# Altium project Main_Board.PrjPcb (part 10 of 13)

## Sheet RJ45.SchDoc: Ethernet
size A3; Organization: Altium Limited; Address1: L3, 12a Rodborough Rd; Address2: Frenchs Forest; Address3: NSW; Address4: Australia 2086
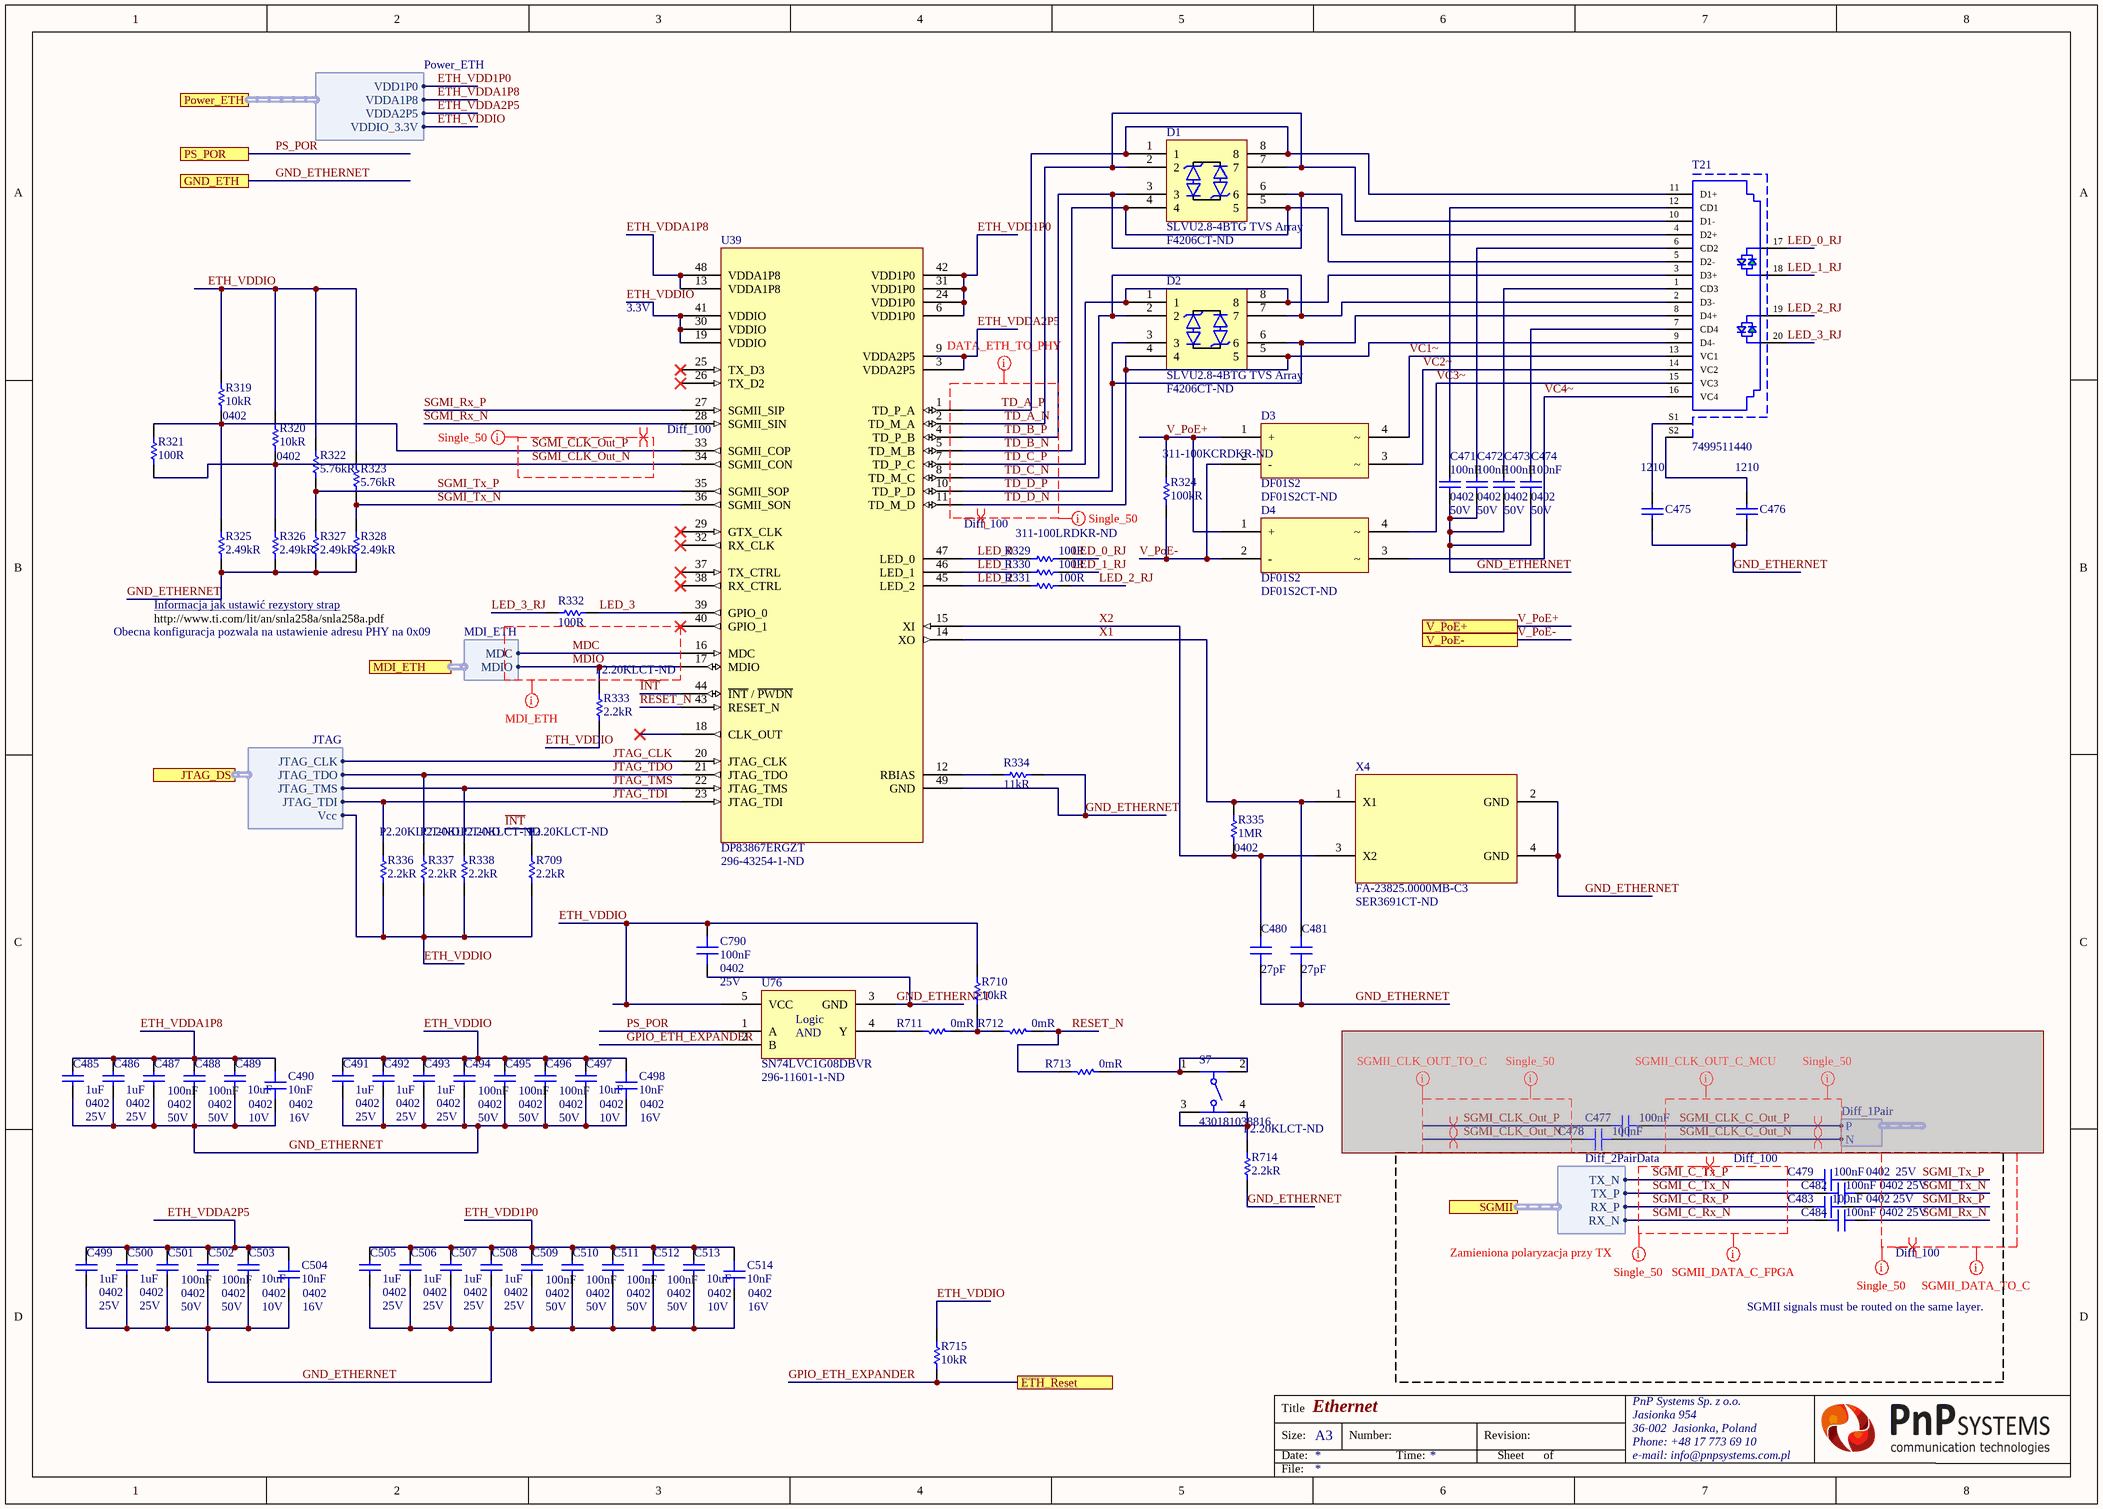
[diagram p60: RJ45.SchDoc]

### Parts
(Parts that share a designator on the sheet are numbered #1, #2 ... from top to bottom, then left to right.)
C471  100nF  Case Code (Imperial): 0402  Voltage: 50V  [CAP 0402/1005 KK]
C472  100nF  Case Code (Imperial): 0402  Voltage: 50V  [CAP 0402/1005 KK]
C473  100nF  Case Code (Imperial): 0402  Voltage: 50V  [CAP 0402/1005 KK]
C474  100nF  Case Code (Imperial): 0402  Voltage: 50V  [CAP 0402/1005 KK]
C475  Case/Package: 1210  [CAPC3326X17L]  (hidden comment: Capacitor_1210)
C476  Case/Package: 1210  [CAPC3326X17L]  (hidden comment: Capacitor_1210)
C477#2  100nF  [CAP 0402/1005 KK]  (masked out: inside a compile mask, not in the netlist)
C478#2  100nF  [CAP 0402/1005 KK]  (masked out: inside a compile mask, not in the netlist)
C479  100nF  Case/Package: 0402  Voltage Rating: 25V  [CAP 0402/1005 KK]
C480  27pF  [CAP 0402/1005 KK]
C481  27pF  [CAP 0402/1005 KK]
C482  100nF  Case/Package: 0402  Voltage Rating: 25V  [CAP 0402/1005 KK]
C483  100nF  Case/Package: 0402  Voltage Rating: 25V  [CAP 0402/1005 KK]
C484  100nF  Case/Package: 0402  Voltage Rating: 25V  [CAP 0402/1005 KK]
C485  1uF  Case/Package: 0402  Voltage Rating: 25V  [CAP 0402/1005 KK]
C486  1uF  Case/Package: 0402  Voltage Rating: 25V  [CAP 0402/1005 KK]
C487  100nF  Case Code (Imperial): 0402  Voltage: 50V  [CAP 0402/1005 KK]
C488  100nF  Case Code (Imperial): 0402  Voltage: 50V  [CAP 0402/1005 KK]
C489  10uF  Case/Package: 0402  Voltage Rating: 10V  [CAP 0402/1005 KK]
C490  10nF  Case/Package: 0402  Voltage Rating (DC): 16V  [CAP 0402/1005 KK]
C491  1uF  Case/Package: 0402  Voltage Rating: 25V  [CAP 0402/1005 KK]
C492  1uF  Case/Package: 0402  Voltage Rating: 25V  [CAP 0402/1005 KK]
C493  1uF  Case/Package: 0402  Voltage Rating: 25V  [CAP 0402/1005 KK]
C494  100nF  Case Code (Imperial): 0402  Voltage: 50V  [CAP 0402/1005 KK]
C495  100nF  Case Code (Imperial): 0402  Voltage: 50V  [CAP 0402/1005 KK]
C496  100nF  Case Code (Imperial): 0402  Voltage: 50V  [CAP 0402/1005 KK]
C497  10uF  Case/Package: 0402  Voltage Rating: 10V  [CAP 0402/1005 KK]
C498  10nF  Case/Package: 0402  Voltage Rating (DC): 16V  [CAP 0402/1005 KK]
C499  1uF  Case/Package: 0402  Voltage Rating: 25V  [CAP 0402/1005 KK]
C500  1uF  Case/Package: 0402  Voltage Rating: 25V  [CAP 0402/1005 KK]
C501  100nF  Case Code (Imperial): 0402  Voltage: 50V  [CAP 0402/1005 KK]
C502  100nF  Case Code (Imperial): 0402  Voltage: 50V  [CAP 0402/1005 KK]
C503  10uF  Case/Package: 0402  Voltage Rating: 10V  [CAP 0402/1005 KK]
C504  10nF  Case/Package: 0402  Voltage Rating (DC): 16V  [CAP 0402/1005 KK]
C505  1uF  Case/Package: 0402  Voltage Rating: 25V  [CAP 0402/1005 KK]
C506  1uF  Case/Package: 0402  Voltage Rating: 25V  [CAP 0402/1005 KK]
C507  1uF  Case/Package: 0402  Voltage Rating: 25V  [CAP 0402/1005 KK]
C508  1uF  Case/Package: 0402  Voltage Rating: 25V  [CAP 0402/1005 KK]
C509  100nF  Case Code (Imperial): 0402  Voltage: 50V  [CAP 0402/1005 KK]
C510  100nF  Case Code (Imperial): 0402  Voltage: 50V  [CAP 0402/1005 KK]
C511  100nF  Case Code (Imperial): 0402  Voltage: 50V  [CAP 0402/1005 KK]
C512  100nF  Case Code (Imperial): 0402  Voltage: 50V  [CAP 0402/1005 KK]
C513  10uF  Case/Package: 0402  Voltage Rating: 10V  [CAP 0402/1005 KK]
C514  10nF  Case/Package: 0402  Voltage Rating (DC): 16V  [CAP 0402/1005 KK]
C790  100nF  Case/Package: 0402  Voltage Rating: 25V  [CAP 0402/1005 KK]
D1  SLVU2.8-4BTG TVS Array  Supplier Part Number 1: F4206CT-ND  [SLVU2.8-4]
D2  SLVU2.8-4BTG TVS Array  Supplier Part Number 1: F4206CT-ND  [SLVU2.8-4]
D3  DF01S2  Supplier Part Number 1: DF01S2CT-ND  [DF005S2 - DF10S2]
D4  DF01S2  Supplier Part Number 1: DF01S2CT-ND  [DF005S2 - DF10S2]
R319  10kR  Case/Package: 0402  [RES 0402/1005 RF KK]
R320  10kR  Case/Package: 0402  [RES 0402/1005 RF KK]
R321  100R  [RES 0402/1005 RF KK]
R322  5.76kR  [RES 0402/1005 RF KK]
R323  5.76kR  [RES 0402/1005 RF KK]
R324  100kR  Supplier Part Number 1: 311-100KCRDKR-ND  [RES 0805/2012 RF]
R325  2.49kR  [RES 0402/1005 RF KK]
R326  2.49kR  [RES 0402/1005 RF KK]
R327  2.49kR  [RES 0402/1005 RF KK]
R328  2.49kR  [RES 0402/1005 RF KK]
R329  100R  Supplier Part Number 1: 311-100LRDKR-ND  [RES 0402/1005 RF KK]
R330  100R  [RES 0402/1005 RF KK]
R331  100R  [RES 0402/1005 RF KK]
R332  100R  [RES 0402/1005 RF KK]
R333  2.2kR  Supplier Part Number 1: P2.20KLCT-ND  [RES 0402/1005 RF KK]
R334  11kR  [RES 0402/1005 RF KK]
R335  1MR  Case/Package: 0402  [RES 0402/1005 RF KK]
R336  2.2kR  Supplier Part Number 1: P2.20KLCT-ND  [RES 0402/1005 RF KK]
R337  2.2kR  Supplier Part Number 1: P2.20KLCT-ND  [RES 0402/1005 RF KK]
R338  2.2kR  Supplier Part Number 1: P2.20KLCT-ND  [RES 0402/1005 RF KK]
R709  2.2kR  Supplier Part Number 1: P2.20KLCT-ND  [RES 0402/1005 RF KK]
R710  10kR  [RES 0402/1005 RF KK]
R711  0mR  [RES 0402/1005 RF KK]
R712  0mR  [RES 0402/1005 RF KK]
R713  0mR  [RES 0402/1005 RF KK]
R714  2.2kR  Supplier Part Number 1: P2.20KLCT-ND  [RES 0402/1005 RF KK]
R715  10kR  [RES 0402/1005 RF KK]
S7  430181038816  [430181038816]
T21  7499511440  [7499511440]
U39  DP83867ERGZT  Supplier Part Number 1: 296-43254-1-ND  [DP83867E]
U76  SN74LVC1G08DBVR  Supplier Part Number 1: 296-11601-1-ND  [SN74LVC1G08DBVR]
X4  FA-23825.0000MB-C3  Supplier Part Number 1: SER3691CT-ND  [FA-23825.0000MB-C3]

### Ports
ETH_Reset, GND_ETH, JTAG_DS (harness JTAG), MDI_ETH (harness MDI_ETH), Power_ETH (harness Power_ETH), PS_POR, SGMII (harness Diff_2PairData), V_PoE+, V_PoE-

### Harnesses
Diff_2PairData: RX_P, RX_N, TX_P, TX_N
Diff_1Pair: P, N
Power_ETH: VDD1P0, VDDA1P8, VDDA2P5, VDDIO_3.3V
MDI_ETH: MDC, MDIO
JTAG: JTAG_CLK, JTAG_TDI, JTAG_TDO, JTAG_TMS, Vcc

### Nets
GND_ETHERNET: C471.1 C472.1 C473.1 C474.1 C475.1 C476.1 C480.1 C481.1 C485.2 C486.2 C487.1 C488.1 C489.1 C490.1 C491.2 C492.2 C493.2 C494.1 C495.1 C496.1 C497.1 C498.1 C499.2 C500.2 C501.1 C502.1 C503.1 C504.1 C505.2 C506.2 C507.2 C508.2 C509.1 C510.1 C511.1 C512.1 C513.1 C514.1 C790.2 R325.1 R326.1 R327.1 R328.1 R334.2 R714.1 U39.49(GND) U76.3(GND) X4.2(GND) X4.4(GND) ; port GND_ETH  [project net B503_Ground]
~{INT}: R709.2 U39.44(~{INT}_/_~{PWDN})
ETH_VDD1P0: C505.1 C506.1 C507.1 C508.1 C509.2 C510.2 C511.2 C512.2 C513.2 C514.2 U39.6(VDD1P0) U39.24(VDD1P0) U39.31(VDD1P0) U39.42(VDD1P0) ; port Power_ETH.VDD1P0  [project net 1V0@1.5A]
ETH_VDDA1P8: C485.1 C486.1 C487.2 C488.2 C489.2 C490.2 U39.13(VDDA1P8) U39.48(VDDA1P8) ; port Power_ETH.VDDA1P8  [project net 1V8@1.5A]
ETH_VDDA2P5: C499.1 C500.1 C501.2 C502.2 C503.2 C504.2 U39.3(VDDA2P5) U39.9(VDDA2P5) ; port Power_ETH.VDDA2P5  [project net 2V5@1.5A]
ETH_VDDIO: C491.1 C492.1 C493.1 C494.2 C495.2 C496.2 C497.2 C498.2 C790.1 R319.2 R320.2 R322.2 R323.2 R333.1 R336.1 R337.1 R338.1 R709.1 R710.2 R715.2 U39.19(VDDIO) U39.30(VDDIO) U39.41(VDDIO) U76.5(VCC) ; port Power_ETH.VDDIO_3.3V, port JTAG_DS.Vcc
GPIO_ETH_EXPANDER: R715.1 U76.2(B) ; port ETH_Reset
JTAG_CLK: U39.20(JTAG_CLK) ; port JTAG_DS.JTAG_CLK
JTAG_TDI: R336.2 U39.23(JTAG_TDI) ; port JTAG_DS.JTAG_TDI
JTAG_TDO: R337.2 U39.21(JTAG_TDO) ; port JTAG_DS.JTAG_TDO
JTAG_TMS: R338.2 U39.22(JTAG_TMS) ; port JTAG_DS.JTAG_TMS
LED_0: R329.1 U39.47(LED_0)
LED_0_RJ: R329.2 T21.17
LED_1: R330.1 U39.46(LED_1)
LED_1_RJ: R330.2 T21.18
LED_2: R331.1 U39.45(LED_2)
LED_2_RJ: R331.2 T21.19
LED_3: R332.2 U39.39(GPIO_0)
LED_3_RJ: R332.1 T21.20
MDC: U39.16(MDC) ; port MDI_ETH.MDC  [project net GEM3_MDC]
MDIO: R333.2 U39.17(MDIO) ; port MDI_ETH.MDIO  [project net GEM3_MDIO]
PS_POR: U76.1(A) ; port PS_POR
RESET_N: R712.1 R713.2 U39.43(RESET_N)
SGMI_C_Rx_N: C484.2 ; port SGMII.RX_N
SGMI_C_Rx_P: C483.2 ; port SGMII.RX_P
SGMI_C_Tx_N: C482.2 ; port SGMII.TX_P
SGMI_C_Tx_P: C479.2 ; port SGMII.TX_N
SGMI_CLK_Out_N: R320.1 R321.1 R326.2 U39.34(SGMII_CON)
SGMI_CLK_Out_P: R319.1 R321.2 R325.2 U39.33(SGMII_COP)
SGMI_Rx_N: C484.1 U39.28(SGMII_SIN)
SGMI_Rx_P: C483.1 U39.27(SGMII_SIP)
SGMI_Tx_N: C482.1 R323.1 R328.2 U39.36(SGMII_SON)
SGMI_Tx_P: C479.1 R322.1 R327.2 U39.35(SGMII_SOP)
TD_A_N: D1.2 D1.7 T21.10(D1-) U39.2(TD_M_A)
TD_A_P: D1.1 D1.8 T21.11(D1+) U39.1(TD_P_A)
TD_B_N: D1.4 D1.5 T21.5(D2-) U39.5(TD_M_B)
TD_B_P: D1.3 D1.6 T21.4(D2+) U39.4(TD_P_B)
TD_C_N: D2.2 D2.7 T21.2(D3-) U39.8(TD_M_C)
TD_C_P: D2.1 D2.8 T21.3(D3+) U39.7(TD_P_C)
TD_D_N: D2.4 D2.5 T21.9(D4-) U39.11(TD_M_D)
TD_D_P: D2.3 D2.6 T21.8(D4+) U39.10(TD_P_D)
V_PoE+: D3.1(+) D4.1(+) R324.2 ; port V_PoE+
V_PoE-: D3.2(-) D4.2(-) R324.1 ; port V_PoE-  [project net PGND]
VC1~: D3.4 T21.13(VC1)
VC2~: D3.3 T21.14(VC2)
VC3~: D4.4 T21.15(VC3)
VC4~: D4.3 T21.16(VC4)
X1: C481.2 R335.2 U39.14(XO) X4.1(X1)
X2: C480.2 R335.1 U39.15(XI) X4.3(X2)
NetC471_2: C471.2 T21.12(CD1)
NetC472_2: C472.2 T21.6(CD2)
NetC473_2: C473.2 T21.1(CD3)
NetC474_2: C474.2 T21.7(CD4)
NetC475_2: C475.2 T21.S1(Shield)
NetC476_2: C476.2 T21.S2(Shield)
NetR334_1: R334.1 U39.12(RBIAS)
NetR710_1: R710.1 R711.1 R712.2
NetR711_2: R711.2 U76.4(Y)
NetR713_1: R713.1 S7.1 S7.2
NetR714_2: R714.2 S7.3 S7.4

Not connected (* = marked no-connect by the designer): U39 18(CLK_OUT)* 25(TX_D3)* 26(TX_D2)* 29(GTX_CLK)* 32(RX_CLK)* 37(TX_CTRL)* 38(RX_CTRL)* 40(GPIO_1)*

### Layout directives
differential pair; differential pair class Diff_100: SGMI_C_Rx_N, SGMI_C_Rx_P, SGMI_C_Tx_N, SGMI_C_Tx_P, SGMI_CLK_C_Out_N, SGMI_CLK_C_Out_P, SGMI_CLK_Out_N, SGMI_CLK_Out_P, SGMI_Rx_N, SGMI_Rx_P, SGMI_Tx_N, SGMI_Tx_P, TD_A_N, TD_A_P, TD_B_N, TD_B_P, TD_C_N, TD_C_P, TD_D_N, TD_D_P
net class DATA_ETH_TO_PHY: TD_A_N, TD_A_P, TD_B_N, TD_B_P, TD_C_N, TD_C_P, TD_D_N, TD_D_P
net class SGMIICLK_TO_CAP: SGMI_CLK_Out_N, SGMI_CLK_Out_P
net class SGMIICLK_CAP_TO_MCU: SGMI_CLK_C_Out_N, SGMI_CLK_C_Out_P
net class SGMII_DATA_C_FPGA: SGMI_C_Rx_N, SGMI_C_Rx_P, SGMI_C_Tx_N, SGMI_C_Tx_P
net class SGMII_DATA_TO_C: SGMI_Rx_N, SGMI_Rx_P, SGMI_Tx_N, SGMI_Tx_P
net class Single_50: SGMI_C_Rx_N, SGMI_C_Rx_P, SGMI_C_Tx_N, SGMI_C_Tx_P, SGMI_CLK_C_Out_N, SGMI_CLK_C_Out_P, SGMI_CLK_Out_N, SGMI_CLK_Out_P, SGMI_Rx_N, SGMI_Rx_P, SGMI_Tx_N, SGMI_Tx_P, TD_A_N, TD_A_P, TD_B_N, TD_B_P, TD_C_N, TD_C_P, TD_D_N, TD_D_P
net class MDI_ETH: MDC, MDIO

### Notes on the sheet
- 3.3V
- Obecna konfiguracja pozwala na ustawienie adresu PHY na 0x09
- http://www.ti.com/lit/an/snla258a/snla258a.pdf
- Informacja jak ustawić rezystory strap <http://www.ti.com/lit/an/snla258a/snla258a.pdf>
- Zamieniona polaryzacja przy TX
- SGMII signals must be routed on the same layer.

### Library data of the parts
C471-C474 C487 C488 C494-C496 C501 C502 C509-C512 = Capacitor: CAP CER 0.1UF 50V X5R 0402; Manufacturer: Murata; Manufacturer Part Number: GRM155R61H104KE14D; Dielectric Material: Ceramic; Dissipation Factor: 0.025%; Tolerance: 10%
C475 C476 = Capacitor_1210: CAP CER 1210 4.7NF 2000V X7R 10%; Manufacturer: KEMET; Manufacturer Part Number: C1210X472KGRACAUTO; Voltage Rating: 2kV
C477#2 C478#2 = Capacitor: Manufacturer: Murata; Manufacturer Part Number: GRM155R71C104KA88D; Dielectric Material: Ceramic; Tolerance: 10%; Voltage Rating: 16V; Dielectric: X7R; Insulation Resistance: 10GR
C479 C482-C484 C790 = Capacitor: Manufacturer: Murata; Manufacturer Part Number: GRM155R71E104KE14J; Tolerance: 10%; Dielectric: X7R
C480 C481 = Capacitor: Manufacturer: KEMET; Manufacturer Part Number: C0402C270K5GACTU; Dielectric Material: Ceramic; Tolerance: 10%; Voltage Rating (DC): 50V; Dielectric: C0G
C485 C486 C491-C493 C499 C500 C505-C508 = Capacitor: MURATA - GRT155R61E105KE01D - SMD Multilayer Ceramic Capacitor, 1 µF, 25 V, 0402 [1005 Metric], ± 10%, X5R, GRT Series - SMD Multilayer Ceramic Capacitor, 1 µF, 25 V, 0402 [1005 Metric], ± 10%, X5R, GRT Series
C489 C497 C503 C513 = Capacitor: CAP CER 10UF 10V X5R 0402; Manufacturer: Samsung; Manufacturer Part Number: CL05A106MP8NUB8; Tolerance: 20%
C490 C498 C504 C514 = Capacitor: Manufacturer: KEMET; Manufacturer Part Number: C0402C103K4RACTU; Dielectric Material: Ceramic; Tolerance: 10%; Dielectric: X7R; Dissipation Factor: 3.5%
D1 D2 = SLVU2.8-4BTG: ESD Suppressor TVS ±30KV 8-Pin SOIC T/R; Manufacturer: Littelfuse; Direction: Bidirectional,Unidirectional; Capacitance: 2.5pF; Operating Supply Voltage: 2.8V; Number of Bidirectional Channels: 4; Min Breakdown Voltage: 3V; Clamping Voltage: 15V; Peak Pulse Power: 600W; Power Line Protection: No; Leakage Current: 1uA; ESD Protection: Yes; Element Configuration: Dual; Peak Pulse Current: 40A
D3 D4 = DF01S2: DIODE BRIDGE 100V 2A SDIP; Manufacturer: ON Semiconductor / Fairchild; Forward Voltage: 1.1V; Max Surge Current: 85A; Peak Reverse Current: 3uA; Reverse Voltage (DC): 70V
R319 R320 R710 R715 = Resistor: Manufacturer 1: Yageo; Manufacturer Part Number 1: RC0402FR-0710KL; Tolerance: 1%; Temperature Coefficient: 100ppm/°C; Voltage Rating: 50V; Power Rating: 62.5mW
R321 R329-R332 = Resistor: RES SMD 100 OHM 1% 1/16W 0402; Manufacturer: Yageo; Manufacturer Part Number: RC0402FR-07100RL; Power Rating: 62.5mW; Voltage Rating: 50V; Temperature Coefficient: 100ppm/°C
R322 R323 = Resistor: Manufacturer: Stackpole Electronics; Manufacturer Part Number: RMCF0402FT5K76; Tolerance: 1%; Max Power Dissipation: 63mW; Temperature Coefficient: 100ppm/°C
R324 = Resistor: RES SMD 100K OHM 1% 1/8W 0805; Manufacturer: Yageo; Manufacturer Part Number: RC0805FR-07100KL; Power Rating: 125mW; Voltage Rating: 150V; Temperature Coefficient: 100ppm/°C
R325-R328 = Resistor: Manufacturer: Stackpole Electronics; Manufacturer Part Number: RMCF0402FT2K49; Tolerance: 1%; Max Power Dissipation: 63mW; Temperature Coefficient: 100ppm/°C
R333 R336-R338 R709 R714 = Resistor: PANASONIC - ERJ2RKF2201X - SMD Chip Resistor, 0402 [1005 Metric], 2.2 kohm, ERJ2R Series, 50 V, Thick Film, 100 mW; Manufacturer Part Number: ERJ-2RKF2201X; Tolerance: 1%; Power Rating: 100mW; Voltage Rating: 50V; Temperature Coefficient: 100ppm/°C
R334 = Resistor: Manufacturer 1: Yageo; Manufacturer Part Number 1: RC0402FR-0711KL; Power Rating: 63mW; Tolerance: 1%; Voltage Rating: 50V; Temperature Coefficient: 100ppm/°C
R335 = Resistor: RES SMD 1M OHM 1% 1/16W 0402; Manufacturer: Yageo; Manufacturer Part Number: RC0402FR-071ML; Power Rating: 63mW; Voltage Rating: 50V; Temperature Coefficient: 100ppm/°C
R711-R713 = Resistor: Manufacturer 1: Yageo; Manufacturer Part Number 1: RC0402JR-070RL; Power Rating: 62.5mW; Tolerance: 5%; Voltage Rating: 50V; Max Power Dissipation: 63mW; Temperature Coefficient: 200ppm/°C
S7 = 430181038816: WS-TASV SMT Tact Switch 4.5x4.5mm, height 3.8mm, 160gf; Rated Voltage: 12VDC; Rated Current: 50mA; Washable: No
T21 = 7499511440: WE-RJ45 LAN Transformer, THT, 10/100/1000 Base-T, Port 1x1, Tab Up; PoE: PoE+ (up to 600 mA); LED: green/yellow-green/yellow; USB: No; Shield Tabs: Yes
U39 = DP83867ERGZT: IC ETHERNET PHY 48VQFN; Manufacturer 1: Texas Instruments; Interface: Serial; Data Rate: 1Gbps; Min Supply Voltage: 950mV; Max Supply Voltage: 2.625V; Cable Length: 130m
U76 = SN74LVC1G08DBVR: IC GATE AND 1CH 2-INP SOT23-5; Manufacturer: Texas Instruments; Min Supply Voltage: 1.65V; Max Supply Voltage: 5.5V; Output Current: 32mA; Number of Inputs: 2; Propagation Delay: 4ns; Number of Outputs: 1; Quiescent Current: 10uA; High Level Output Current: -32mA; Turn-On Delay Time: 4.5ns
X4 = FA-23825.0000MB-C3: CRYSTAL 25.0000MHZ 18PF SMD; Manufacturer 1: Epson; Frequency: 25MHz; Frequency Tolerance: 50ppm; ESR (Equivalent Series Resistance): 50R; Frequency Stability: 30ppm

## Sheet Sata.SchDoc: NVMe
size A3; Organization: Altium Limited; Address1: L3, 12a Rodborough Rd; Address2: Frenchs Forest; Address3: NSW; Address4: Australia 2086
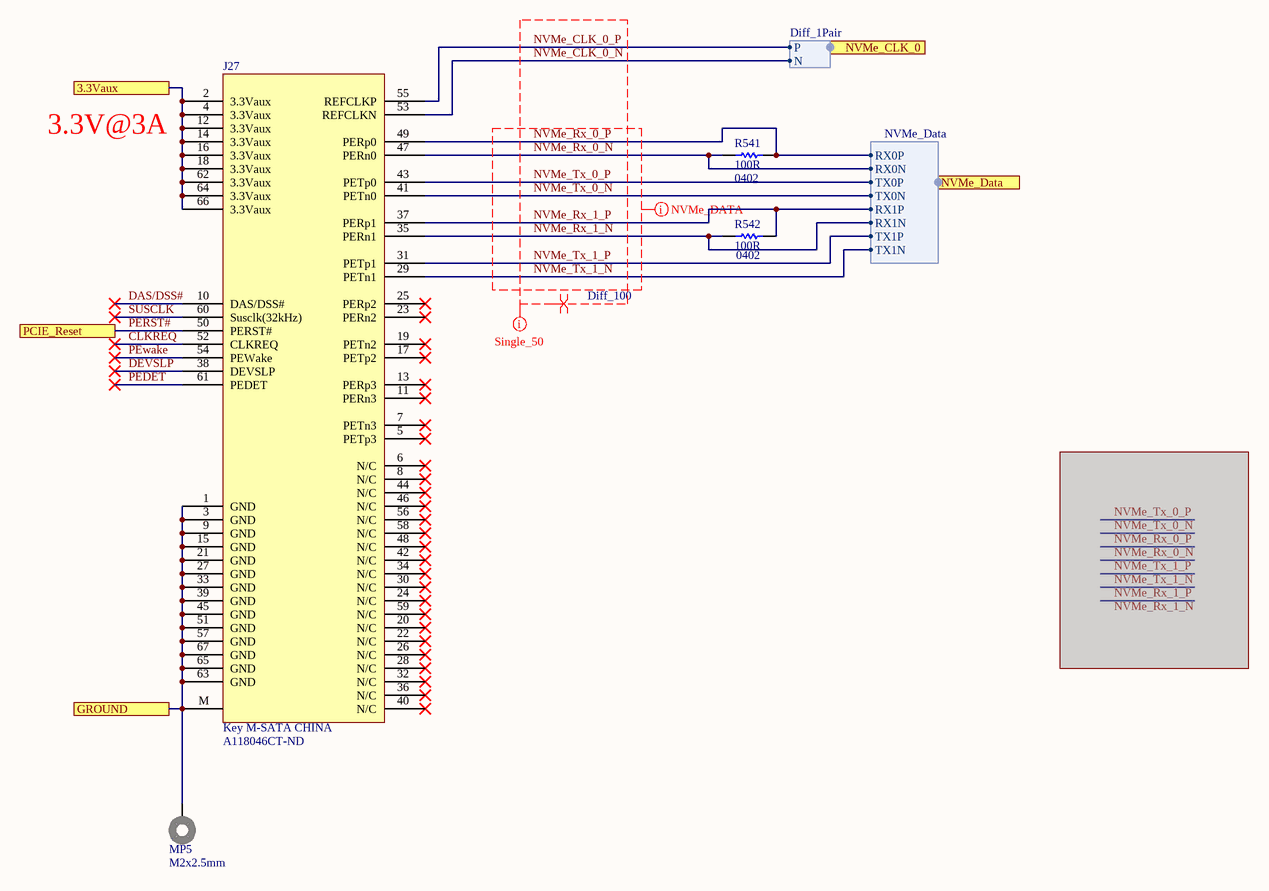
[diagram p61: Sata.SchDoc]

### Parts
J27  Key M-SATA CHINA  Supplier Part Number 1: A118046CT-ND  [M.2 KEY M - NVMe]
MP5  M2x2.5mm  [9774025243]
R541  100R  Case/Package: 0402  [RES 0402/1005 RF KK]
R542  100R  Case/Package: 0402  [RES 0402/1005 RF KK]

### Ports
3.3Vaux, GROUND, NVMe_CLK_0 (harness Diff_1Pair), NVMe_Data (harness NVMe_Data), PCIE_Reset

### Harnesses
Diff_1Pair: P, N
NVMe_Data: RX0P, RX0N, TX0P, TX0N, RX1P, RX1N, TX1P, TX1N

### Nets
B503_Ground: J27.1(GND) J27.3(GND) J27.9(GND) J27.15(GND) J27.21(GND) J27.27(GND) J27.33(GND) J27.39(GND) J27.45(GND) J27.51(GND) J27.57(GND) J27.63(GND) J27.65(GND) J27.67(GND) J27.M MP5.1 ; port GROUND
3V3_NVMe: J27.2(3.3Vaux) J27.4(3.3Vaux) J27.12(3.3Vaux) J27.14(3.3Vaux) J27.16(3.3Vaux) J27.18(3.3Vaux) J27.62(3.3Vaux) J27.64(3.3Vaux) J27.66(3.3Vaux) ; port 3.3Vaux
CLKREQ: J27.52(CLKREQ)
DAS/DSS#: J27.10(DAS/DSS#)
DEVSLP: J27.38(DEVSLP)
NVMe_CLK_0_N: J27.53(REFCLKN) ; port NVMe_CLK_0.N  [project net LTC6952_0_MATCH_Out6_N]
NVMe_CLK_0_P: J27.55(REFCLKP) ; port NVMe_CLK_0.P  [project net LTC6952_0_MATCH_Out6_P]
NVMe_Rx_0_N: J27.47(PERn0) R541.2 ; port NVMe_Data.RX0N
NVMe_Rx_0_P: J27.49(PERp0) R541.1 ; port NVMe_Data.RX0P
NVMe_Rx_1_N: J27.35(PERn1) R542.1 ; port NVMe_Data.RX1N
NVMe_Rx_1_P: J27.37(PERp1) R542.2 ; port NVMe_Data.RX1P
NVMe_Tx_0_N: J27.41(PETn0) ; port NVMe_Data.TX0N
NVMe_Tx_0_P: J27.43(PETp0) ; port NVMe_Data.TX0P
NVMe_Tx_1_N: J27.29(PETn1) ; port NVMe_Data.TX1N
NVMe_Tx_1_P: J27.31(PETp1) ; port NVMe_Data.TX1P
PEDET: J27.61(PEDET)
PERST#: J27.50(PERST#) ; port PCIE_Reset  [project net PCIe_RESET]
PEwake: J27.54(PEWake)
SUSCLK: J27.60(Susclk(32kHz))

Not connected (* = marked no-connect by the designer): J27 5(PETp3)* 6(N/C)* 7(PETn3)* 8(N/C)* 11(PERn3)* 13(PERp3)* 17(PETp2)* 19(PETn2)* 20(N/C)* 22(N/C)* 23(PERn2)* 24(N/C)* 25(PERp2)* 26(N/C)* 28(N/C)* 30(N/C)* 32(N/C)* 34(N/C)* 36(N/C)* 40(N/C)* 42(N/C)* 44(N/C)* 46(N/C)* 48(N/C)* 56(N/C)* 58(N/C)* 59(N/C)*

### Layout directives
net class NVMe_DATA: NVMe_Rx_0_N, NVMe_Rx_0_P, NVMe_Rx_1_N, NVMe_Rx_1_P, NVMe_Tx_0_N, NVMe_Tx_0_P, NVMe_Tx_1_N, NVMe_Tx_1_P
differential pair; differential pair class Diff_100: NVMe_CLK_0_N, NVMe_CLK_0_P, NVMe_Rx_0_N, NVMe_Rx_0_P, NVMe_Rx_1_N, NVMe_Rx_1_P, NVMe_Tx_0_N, NVMe_Tx_0_P, NVMe_Tx_1_N, NVMe_Tx_1_P
net class Single_50: NVMe_CLK_0_N, NVMe_CLK_0_P, NVMe_Rx_0_N, NVMe_Rx_0_P, NVMe_Rx_1_N, NVMe_Rx_1_P, NVMe_Tx_0_N, NVMe_Tx_0_P, NVMe_Tx_1_N, NVMe_Tx_1_P

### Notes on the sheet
- 3.3V@3A

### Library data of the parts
J27 = 1-2199230-6_CHINA: CONN EDGE DUAL FMALE 67POS 0.020; Manufacturer 1: TE Connectivity; Number of Positions: 67; PCB Mounting Orientation: Right Angle; Contact Current Rating: 500mA; Pitch: 0.5mm
MP5 = 9774025243R: WA-SMSI SMT Steel Spacer, OD4.35mm, M2x2.5mm; Inner Diameter: 2.8mm; Outer Diameter: 4.35mm; Surface: Tin; Thread: M2
R541 R542 = Resistor: as R321 on sheet RJ45

## Sheet uSD.SchDoc: uSD
size A4
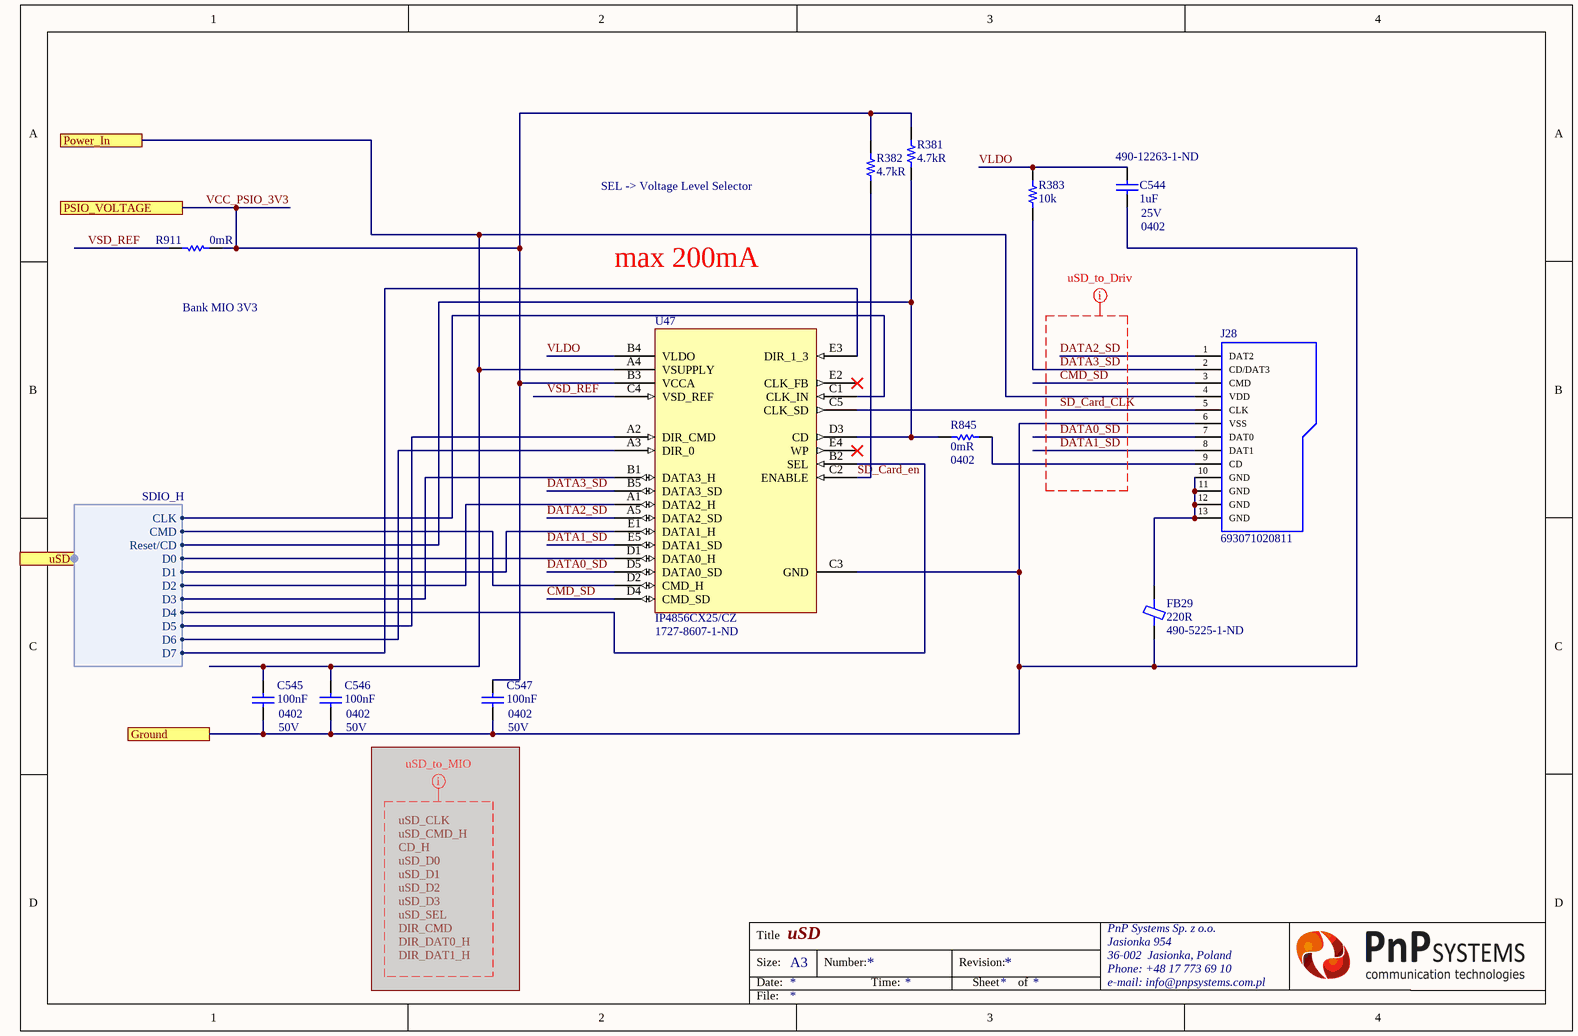
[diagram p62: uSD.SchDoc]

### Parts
(Parts that share a designator on the sheet are numbered #1, #2 ... from top to bottom, then left to right.)
C544  1uF  Supplier Part Number 1: 490-12263-1-ND  Case/Package: 0402  Voltage Rating: 25V  [CAP 0402/1005 KK]
C545  100nF  Case Code (Imperial): 0402  Voltage: 50V  [CAP 0402/1005 KK]
C546  100nF  Case Code (Imperial): 0402  Voltage: 50V  [CAP 0402/1005 KK]
C547  100nF  Case Code (Imperial): 0402  Voltage: 50V  [CAP 0402/1005 KK]
FB29  220R  Supplier Part Number 1: 490-5225-1-ND  [FER 0603/1608]
J28  693071020811  [693071020811]
R381  4.7kR  [RES 0402/1005 RF KK]
R382  4.7kR  [RES 0402/1005 RF KK]
R383  10k  [RES 0402/1005 RF KK]
R845#2  0mR  Case/Package: 0402  [RES 0402/1005 RF KK]
R911  0mR  [RES 0402/1005 RF KK]
U47  IP4856CX25/CZ  Supplier Part Number 1: 1727-8607-1-ND  [IP4856CX25/C]

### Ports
Ground, Power_In, PSIO_VOLTAGE, uSD (harness SDIO_H)

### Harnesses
SDIO_H: CLK, CMD, Reset/CD, D0, D1, D2, D3, D4, D5, D6, D7

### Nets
B503_Ground: C544.1 C545.1 C546.1 C547.1 FB29.2 J28.6(VSS) U47.C3(GND) ; port Ground
3V3_RAIL: C545.2 C546.2 J28.4(VDD) U47.A4(VSUPPLY) ; port Power_In
CMD_SD: J28.3(CMD) U47.D4(CMD_SD)
DATA0_SD: J28.7(DAT0) U47.D5(DATA0_SD)
DATA1_SD: J28.8(DAT1) U47.E5(DATA1_SD)
DATA2_SD: J28.1(DAT2) U47.A5(DATA2_SD)
DATA3_SD: J28.2(CD/DAT3) R383.2 U47.B5(DATA3_SD)
SD_Card_CLK: J28.5(CLK) U47.C5(CLK_SD)
SD_Card_en: R382.1 U47.C2(ENABLE)
uSD_CD: R381.1 R845#2.2 U47.D3(CD) ; port uSD.Reset/CD
uSD_CLK: U47.C1(CLK_IN) ; port uSD.CLK
uSD_CMD: U47.D2(CMD_H) ; port uSD.CMD
uSD_D0: U47.D1(DATA0_H) ; port uSD.D0
uSD_D1: U47.E1(DATA1_H) ; port uSD.D1
uSD_D2: U47.A1(DATA2_H) ; port uSD.D2
uSD_D3: U47.B1(DATA3_H) ; port uSD.D3
uSD_D4: U47.B2(SEL) ; port uSD.D4
uSD_D5: U47.A2(DIR_CMD) ; port uSD.D5
uSD_D6: U47.A3(DIR_0) ; port uSD.D6
uSD_D7: U47.E3(DIR_1_3) ; port uSD.D7
VCC_PSIO_3V3: C547.2 R381.2 R382.2 R911.1 U47.B3(VCCA) ; port PSIO_VOLTAGE  [project net ETH_VDDIO]
VLDO: C544.2 R383.1 U47.B4(VLDO)
VSD_REF: R911.2 U47.C4(VSD_REF)
NetFB29_1: FB29.1 J28.10(GND) J28.11(GND) J28.12(GND) J28.13(GND)
NetJ28_9: J28.9(CD) R845#2.1

Not connected (* = marked no-connect by the designer): U47 E2(CLK_FB)* E4(WP)*

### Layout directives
net class uSD_to_MIO: CD_H, DIR_CMD, DIR_DAT0_H, DIR_DAT1_H, uSD_CLK, uSD_CMD_H, uSD_D0, uSD_D1, uSD_D2, uSD_D3, uSD_SEL
net class uSD_to_Driv: CMD_SD, DATA0_SD, DATA1_SD, DATA2_SD, DATA3_SD, SD_Card_CLK

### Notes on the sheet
- SEL -> Voltage Level Selector
- Bank MIO 3V3
- max 200mA

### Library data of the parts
C544 = Capacitor: as C485 on sheet RJ45
C545-C547 = Capacitor: as C471-C474 on sheet RJ45
FB29 = Ferrite: FERRITE BEAD 220 OHM 0603 1LN; Manufacturer: Murata; Manufacturer Part Number: BLM18SG221TN1D; Material: Ferrite,Steel; Tolerance: 25%; Max Current Rating: 2.5A; Number of Lines: 1; DC Resistance (DCR): 40mR; Test Frequency: 100MHz
J28 = 693071020811: WR-CRD Micro SD Card Connector Push & Push; Contact Resistance: 100mOhm; Gender: Socket; Pin Number: 8; Working Voltage: 30VAC; Withstanding Voltage: 500VAC; Rated Current: 0.5A
R381 R382 = Resistor: Manufacturer: Panasonic; Manufacturer Part Number: ERJ-2RKF4701X; Tolerance: 1%; Temperature Coefficient: 100ppm/°C; Power Rating: 100mW; Voltage Rating: 50V
R383 = Resistor: SMT Resistor
R845#2 R911 = Resistor: as R711-R713 on sheet RJ45
U47 = IP4856CX25/CZ: Memory Card Interface 25-WLCSP (2.04x2.04); Manufacturer 1: Nexperia USA

## Sheet FTDI.SchDoc
size A3; Organization: Altium Limited; Address1: L3, 12a Rodborough Rd; Address2: Frenchs Forest; Address3: NSW; Address4: Australia 2086
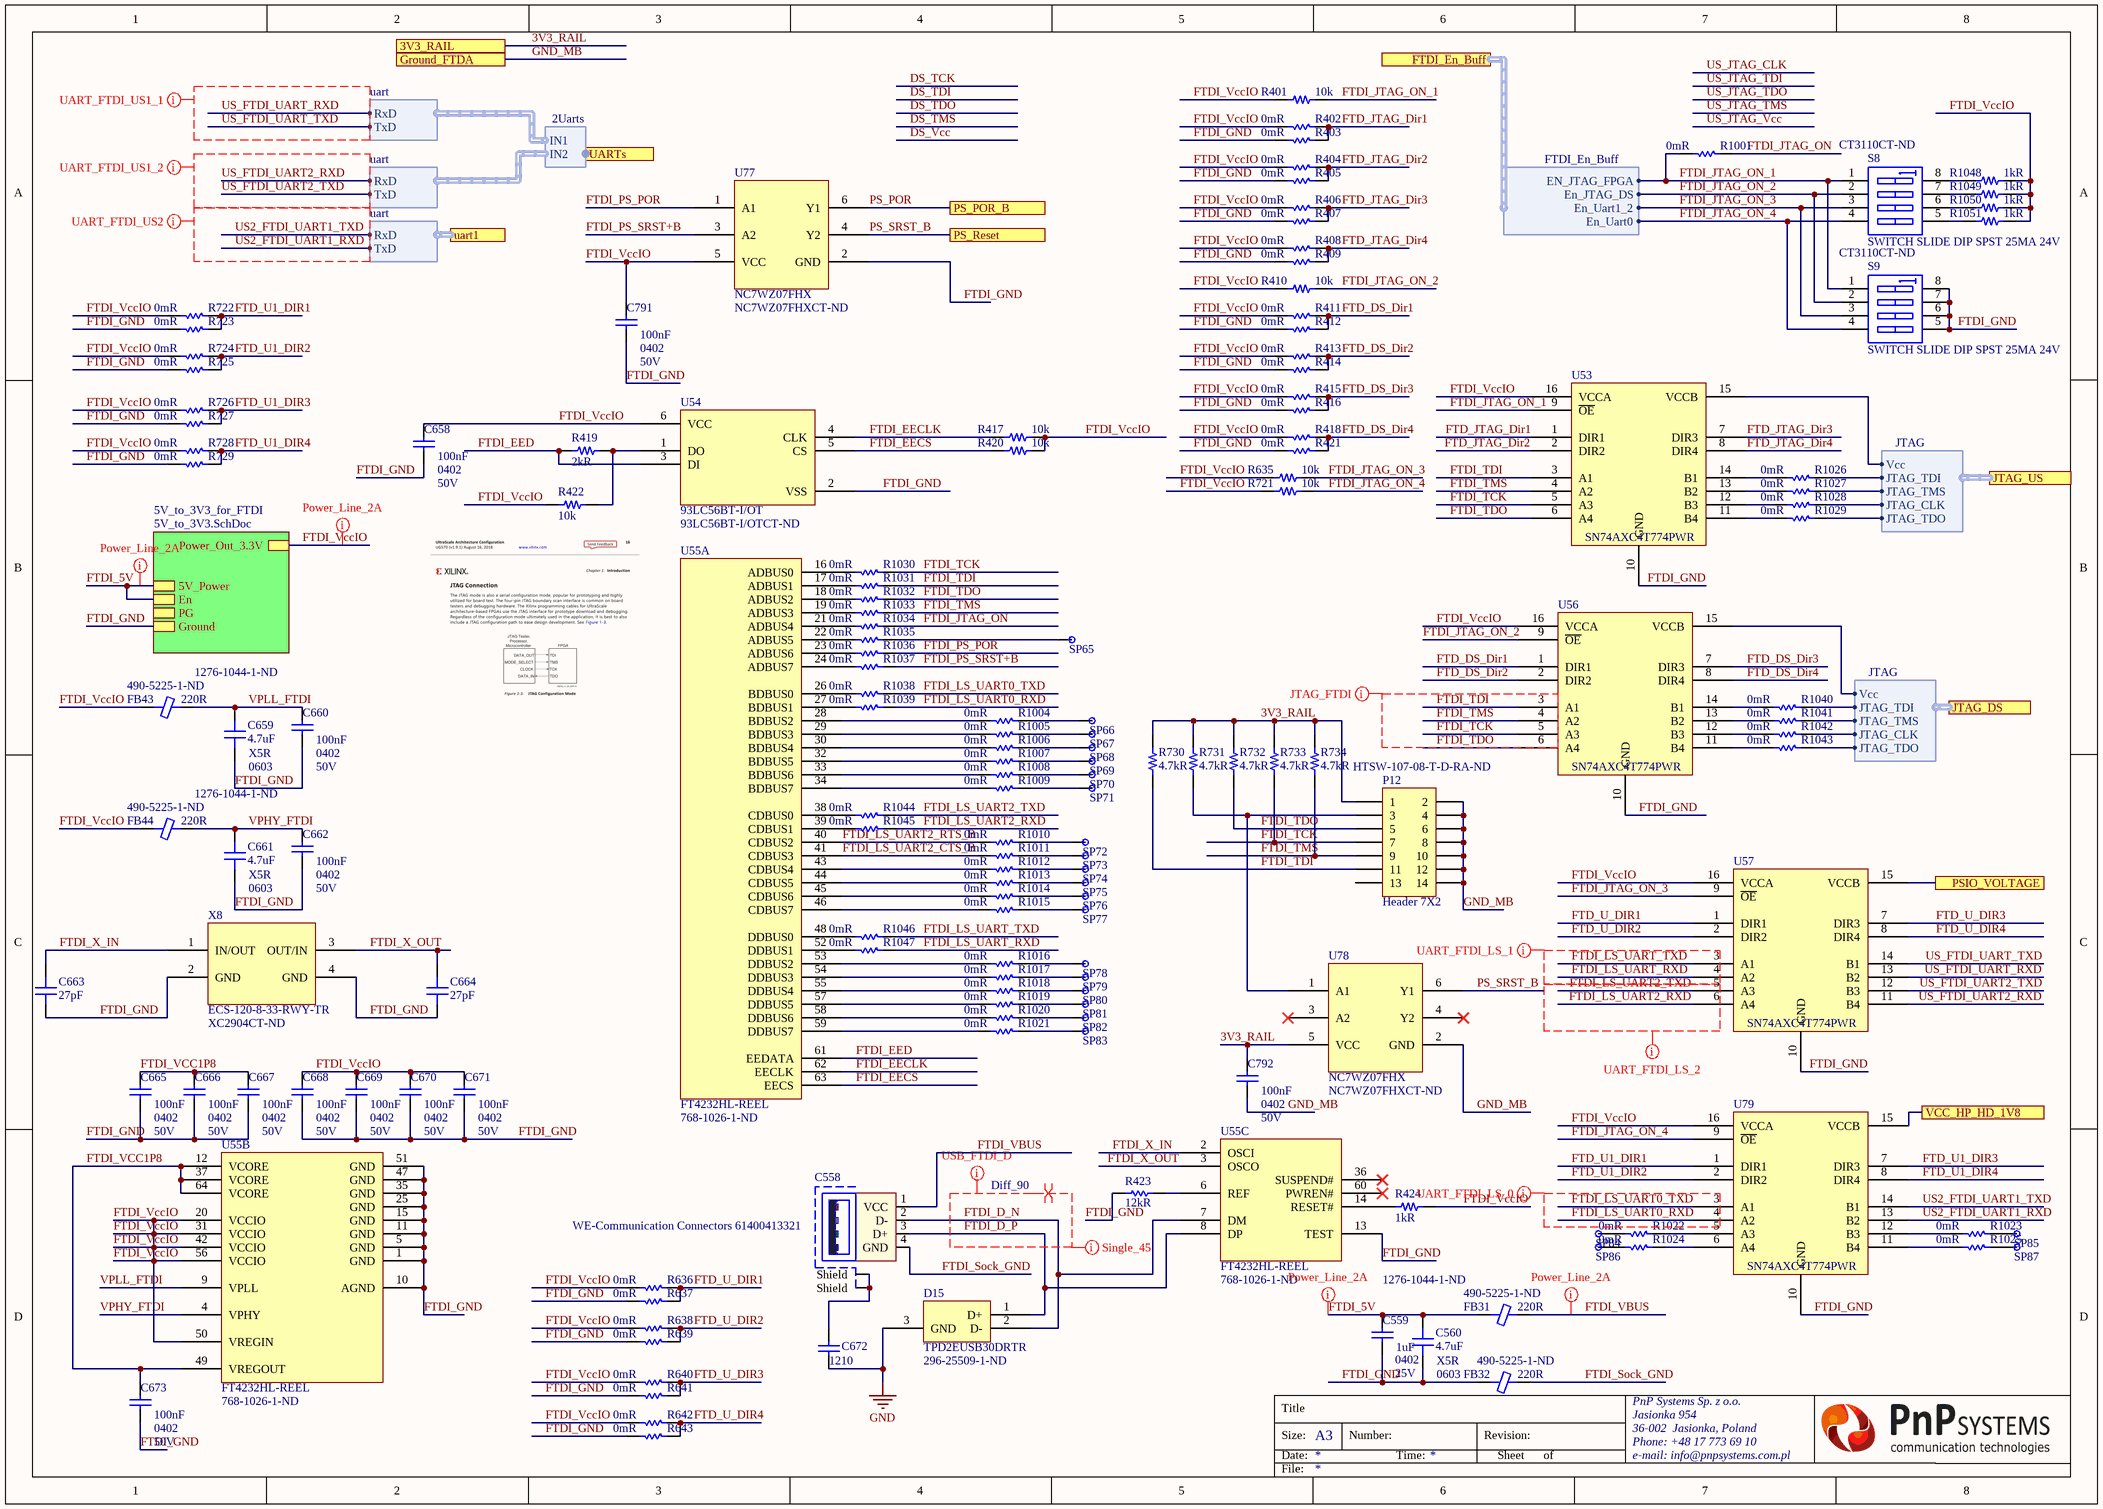
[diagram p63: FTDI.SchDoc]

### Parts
C558  WE-Communication Connectors 61400413321  [61400413321]
C559  1uF  Case/Package: 0402  Voltage Rating: 25V  [CAP 0402/1005 KK]
C560  4.7uF  Supplier Part Number 1: 1276-1044-1-ND  Case/Package: 0603  Dielectric: X5R  [CAP 0603/1608 RF]
C658  100nF  Case Code (Imperial): 0402  Voltage: 50V  [CAP 0402/1005 KK]
C659  4.7uF  Supplier Part Number 1: 1276-1044-1-ND  Case/Package: 0603  Dielectric: X5R  [CAP 0603/1608 RF]
C660  100nF  Case Code (Imperial): 0402  Voltage: 50V  [CAP 0402/1005 KK]
C661  4.7uF  Supplier Part Number 1: 1276-1044-1-ND  Case/Package: 0603  Dielectric: X5R  [CAP 0603/1608 RF]
C662  100nF  Case Code (Imperial): 0402  Voltage: 50V  [CAP 0402/1005 KK]
C663  27pF  [CAP 0402/1005 KK]
C664  27pF  [CAP 0402/1005 KK]
C665  100nF  Case Code (Imperial): 0402  Voltage: 50V  [CAP 0402/1005 KK]
C666  100nF  Case Code (Imperial): 0402  Voltage: 50V  [CAP 0402/1005 KK]
C667  100nF  Case Code (Imperial): 0402  Voltage: 50V  [CAP 0402/1005 KK]
C668  100nF  Case Code (Imperial): 0402  Voltage: 50V  [CAP 0402/1005 KK]
C669  100nF  Case Code (Imperial): 0402  Voltage: 50V  [CAP 0402/1005 KK]
C670  100nF  Case Code (Imperial): 0402  Voltage: 50V  [CAP 0402/1005 KK]
C671  100nF  Case Code (Imperial): 0402  Voltage: 50V  [CAP 0402/1005 KK]
C672  Case/Package: 1210  [CAPC3326X17L]  (hidden comment: Capacitor_1210)
C673  100nF  Case Code (Imperial): 0402  Voltage: 50V  [CAP 0402/1005 KK]
C791  100nF  Case Code (Imperial): 0402  Voltage: 50V  [CAP 0402/1005 KK]
C792  100nF  Case Code (Imperial): 0402  Voltage: 50V  [CAP 0402/1005 KK]
D15  TPD2EUSB30DRTR  Supplier Part Number 1: 296-25509-1-ND  [TPD2EUSB30]
FB31  220R  Supplier Part Number 1: 490-5225-1-ND  [FER 0603/1608]
FB32  220R  Supplier Part Number 1: 490-5225-1-ND  [FER 0603/1608]
FB43  220R  Supplier Part Number 1: 490-5225-1-ND  [FER 0603/1608]
FB44  220R  Supplier Part Number 1: 490-5225-1-ND  [FER 0603/1608]
P12  Header 7X2  Supplier Part Number 1: HTSW-107-08-T-D-RA-ND  [HDR2X7]
R401  10k  [RES 0402/1005 RF KK]
R402  0mR  [RES 0402/1005 RF KK]
R403  0mR  [RES 0402/1005 RF KK]
R404  0mR  [RES 0402/1005 RF KK]
R405  0mR  [RES 0402/1005 RF KK]
R406  0mR  [RES 0402/1005 RF KK]
R407  0mR  [RES 0402/1005 RF KK]
R408  0mR  [RES 0402/1005 RF KK]
R409  0mR  [RES 0402/1005 RF KK]
R410  10k  [RES 0402/1005 RF KK]
R411  0mR  [RES 0402/1005 RF KK]
R412  0mR  [RES 0402/1005 RF KK]
R413  0mR  [RES 0402/1005 RF KK]
R414  0mR  [RES 0402/1005 RF KK]
R415  0mR  [RES 0402/1005 RF KK]
R416  0mR  [RES 0402/1005 RF KK]
R417  10k  [RES 0402/1005 RF KK]
R418  0mR  [RES 0402/1005 RF KK]
R419  2kR  [RES 0402/1005 RF KK]
R420  10k  [RES 0402/1005 RF KK]
R421  0mR  [RES 0402/1005 RF KK]
R422  10k  [RES 0402/1005 RF KK]
R423  12kR  [RES 0402/1005 RF KK]
R424  1kR  [RES 0402/1005 RF KK]
R635  10k  [RES 0402/1005 RF KK]
R636  0mR  [RES 0402/1005 RF KK]
R637  0mR  [RES 0402/1005 RF KK]
R638  0mR  [RES 0402/1005 RF KK]
R639  0mR  [RES 0402/1005 RF KK]
R640  0mR  [RES 0402/1005 RF KK]
R641  0mR  [RES 0402/1005 RF KK]
R642  0mR  [RES 0402/1005 RF KK]
R643  0mR  [RES 0402/1005 RF KK]
R721  10k  [RES 0402/1005 RF KK]
R722  0mR  [RES 0402/1005 RF KK]
R723  0mR  [RES 0402/1005 RF KK]
R724  0mR  [RES 0402/1005 RF KK]
R725  0mR  [RES 0402/1005 RF KK]
R726  0mR  [RES 0402/1005 RF KK]
R727  0mR  [RES 0402/1005 RF KK]
R728  0mR  [RES 0402/1005 RF KK]
R729  0mR  [RES 0402/1005 RF KK]
R730  4.7kR  [RES 0402/1005 RF KK]
R731  4.7kR  [RES 0402/1005 RF KK]
R732  4.7kR  [RES 0402/1005 RF KK]
R733  4.7kR  [RES 0402/1005 RF KK]
R734  4.7kR  [RES 0402/1005 RF KK]
R1001  0mR  [RES 0402/1005 RF KK]
R1004  0mR  [RES 0402/1005 RF KK]
R1005  0mR  [RES 0402/1005 RF KK]
R1006  0mR  [RES 0402/1005 RF KK]
R1007  0mR  [RES 0402/1005 RF KK]
R1008  0mR  [RES 0402/1005 RF KK]
R1009  0mR  [RES 0402/1005 RF KK]
R1010  0mR  [RES 0402/1005 RF KK]
R1011  0mR  [RES 0402/1005 RF KK]
R1012  0mR  [RES 0402/1005 RF KK]
R1013  0mR  [RES 0402/1005 RF KK]
R1014  0mR  [RES 0402/1005 RF KK]
R1015  0mR  [RES 0402/1005 RF KK]
R1016  0mR  [RES 0402/1005 RF KK]
R1017  0mR  [RES 0402/1005 RF KK]
R1018  0mR  [RES 0402/1005 RF KK]
R1019  0mR  [RES 0402/1005 RF KK]
R1020  0mR  [RES 0402/1005 RF KK]
R1021  0mR  [RES 0402/1005 RF KK]
R1022  0mR  [RES 0402/1005 RF KK]
R1023  0mR  [RES 0402/1005 RF KK]
R1024  0mR  [RES 0402/1005 RF KK]
R1025  0mR  [RES 0402/1005 RF KK]
R1026  0mR  [RES 0402/1005 RF KK]
R1027  0mR  [RES 0402/1005 RF KK]
R1028  0mR  [RES 0402/1005 RF KK]
R1029  0mR  [RES 0402/1005 RF KK]
R1030  0mR  [RES 0402/1005 RF KK]
R1031  0mR  [RES 0402/1005 RF KK]
R1032  0mR  [RES 0402/1005 RF KK]
R1033  0mR  [RES 0402/1005 RF KK]
R1034  0mR  [RES 0402/1005 RF KK]
R1035  0mR  [RES 0402/1005 RF KK]
R1036  0mR  [RES 0402/1005 RF KK]
R1037  0mR  [RES 0402/1005 RF KK]
R1038  0mR  [RES 0402/1005 RF KK]
R1039  0mR  [RES 0402/1005 RF KK]
R1040  0mR  [RES 0402/1005 RF KK]
R1041  0mR  [RES 0402/1005 RF KK]
R1042  0mR  [RES 0402/1005 RF KK]
R1043  0mR  [RES 0402/1005 RF KK]
R1044  0mR  [RES 0402/1005 RF KK]
R1045  0mR  [RES 0402/1005 RF KK]
R1046  0mR  [RES 0402/1005 RF KK]
R1047  0mR  [RES 0402/1005 RF KK]
R1048  1kR  [RES 0402/1005 RF KK]
R1049  1kR  [RES 0402/1005 RF KK]
R1050  1kR  [RES 0402/1005 RF KK]
R1051  1kR  [RES 0402/1005 RF KK]
S8  SWITCH SLIDE DIP SPST 25MA 24V  Supplier Part Number 1: CT3110CT-ND  [SO8_N]
S9  SWITCH SLIDE DIP SPST 25MA 24V  Supplier Part Number 1: CT3110CT-ND  [SO8_N]
SP65  SP  [MeasureTP]  (value not drawn)
SP66  SP  [MeasureTP]  (value not drawn)
SP67  SP  [MeasureTP]  (value not drawn)
SP68  SP  [MeasureTP]  (value not drawn)
SP69  SP  [MeasureTP]  (value not drawn)
SP70  SP  [MeasureTP]  (value not drawn)
SP71  SP  [MeasureTP]  (value not drawn)
SP72  SP  [MeasureTP]  (value not drawn)
SP73  SP  [MeasureTP]  (value not drawn)
SP74  SP  [MeasureTP]  (value not drawn)
SP75  SP  [MeasureTP]  (value not drawn)
SP76  SP  [MeasureTP]  (value not drawn)
SP77  SP  [MeasureTP]  (value not drawn)
SP78  SP  [MeasureTP]  (value not drawn)
SP79  SP  [MeasureTP]  (value not drawn)
SP80  SP  [MeasureTP]  (value not drawn)
SP81  SP  [MeasureTP]  (value not drawn)
SP82  SP  [MeasureTP]  (value not drawn)
SP83  SP  [MeasureTP]  (value not drawn)
SP84  SP  [MeasureTP]  (value not drawn)
SP85  SP  [MeasureTP]  (value not drawn)
SP86  SP  [MeasureTP]  (value not drawn)
SP87  SP  [MeasureTP]  (value not drawn)
U53  SN74AXC4T774PWR  [SN74AXC4T774PWR]
U54  93LC56BT-I/OT  Supplier Part Number 1: 93LC56BT-I/OTCT-ND  [93LC56BT]
U55  FT4232HL-REEL  Supplier Part Number 1: 768-1026-1-ND  [FT4232HL]  (parts A,B,C of 3)
U56  SN74AXC4T774PWR  [SN74AXC4T774PWR]
U57  SN74AXC4T774PWR  [SN74AXC4T774PWR]
U77  NC7WZ07FHX  Supplier Part Number 1: NC7WZ07FHXCT-ND  [NC7WZ07FHX]
U78  NC7WZ07FHX  Supplier Part Number 1: NC7WZ07FHXCT-ND  [NC7WZ07FHX]
U79  SN74AXC4T774PWR  [SN74AXC4T774PWR]
X8  ECS-120-8-33-RWY-TR  Supplier Part Number 1: XC2904CT-ND  [ECS-120-8-33-RWY-TR]

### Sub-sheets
5V_to_3V3_for_FTDI = 5V_to_3V3.SchDoc: En, 5V_Power, PG, Ground, Power_Out_3.3V

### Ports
3V3_RAIL, FTDI_En_Buff (harness FTDI_En_Buff), Ground_FTDA, JTAG_DS (harness JTAG), JTAG_US (harness JTAG), PS_POR_B, PS_Reset, PSIO_VOLTAGE, uart1 (harness uart), UARTs (harness 2Uarts), VCC_HP_HD_1V8

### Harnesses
uart: RxD, TxD
JTAG: JTAG_CLK, JTAG_TDI, JTAG_TDO, JTAG_TMS, Vcc
FTDI_En_Buff: EN_JTAG_FPGA, En_JTAG_DS, En_Uart1_2, En_Uart0
2Uarts: IN1, IN2

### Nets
GND: C672.1 C792.1 D15.3(GND) P12.2 P12.4 P12.6 P12.8 P12.10 P12.12 P12.14 U78.2(GND) ; port Ground_FTDA  [also labelled GND_MB]  [project net B503_Ground]
3V3_RAIL: C792.2 P12.1 R730.2 R731.2 R732.2 R733.2 R734.2 U78.5(VCC) ; port 3V3_RAIL
ETH_VDDIO: U53.15(VCCB) U56.15(VCCB) U57.15(VCCB) ; port PSIO_VOLTAGE, port JTAG_DS.Vcc, port JTAG_US.Vcc
FTD_DS_Dir1: R411.2 R412.2 U56.1(DIR1)
FTD_DS_Dir2: R413.2 R414.2 U56.2(DIR2)
FTD_DS_Dir3: R415.2 R416.2 U56.7(DIR3)
FTD_DS_Dir4: R418.2 R421.2 U56.8(DIR4)
FTD_JTAG_Dir1: R402.2 R403.2 U53.1(DIR1)
FTD_JTAG_Dir2: R404.2 R405.2 U53.2(DIR2)
FTD_JTAG_Dir3: R406.2 R407.2 U53.7(DIR3)
FTD_JTAG_Dir4: R408.2 R409.2 U53.8(DIR4)
FTD_U1_DIR1: R722.2 R723.2 U79.1(DIR1)
FTD_U1_DIR2: R724.2 R725.2 U79.2(DIR2)
FTD_U1_DIR3: R726.2 R727.2 U79.7(DIR3)
FTD_U1_DIR4: R728.2 R729.2 U79.8(DIR4)
FTD_U_DIR1: R636.2 R637.2 U57.1(DIR1)
FTD_U_DIR2: R638.2 R639.2 U57.2(DIR2)
FTD_U_DIR3: R640.2 R641.2 U57.7(DIR3)
FTD_U_DIR4: R642.2 R643.2 U57.8(DIR4)
FTDI_5V: C559.1 C560.2 FB31.1 ; sheet 5V_to_3V3_for_FTDI/En, sheet 5V_to_3V3_for_FTDI/5V_Power
FTDI_D_N: C558.2(D-) D15.2(D-) U55.7(DM)
FTDI_D_P: C558.3(D+) D15.1(D+) U55.8(DP)
FTDI_EECLK: R417.2 U54.4(CLK) U55.62(EECLK)
FTDI_EECS: R420.2 U54.5(CS) U55.63(EECS)
FTDI_EED: R419.1 U54.3(DI) U55.61(EEDATA)
FTDI_GND: C559.2 C560.1 C658.1 C659.1 C660.1 C661.1 C662.1 C663.1 C664.1 C665.1 C666.1 C667.1 C668.1 C669.1 C670.1 C671.1 C673.1 C791.1 FB32.1 R403.1 R405.1 R407.1 R409.1 R412.1 R414.1 R416.1 R421.1 R423.2 R637.1 R639.1 R641.1 R643.1 R723.1 R725.1 R727.1 R729.1 S9.5(B4) S9.6(B3) S9.7(B2) S9.8(B1) U53.10(GND) U54.2(VSS) U55.1(GND) U55.5(GND) U55.10(AGND) U55.11(GND) U55.13(TEST) U55.15(GND) U55.25(GND) U55.35(GND) U55.47(GND) U55.51(GND) U56.10(GND) U57.10(GND) U77.2(GND) U79.10(GND) X8.2(GND) X8.4(GND) ; sheet 5V_to_3V3_for_FTDI/Ground
FTDI_JTAG_ON: R1001.2 R1034.2
FTDI_JTAG_ON_1: R401.1 R1001.1 S8.1(A1) S9.1(A1) U53.9(~{OE}) ; port FTDI_En_Buff.EN_JTAG_FPGA
FTDI_JTAG_ON_2: R410.1 S8.2(A2) S9.2(A2) U56.9(~{OE}) ; port FTDI_En_Buff.En_JTAG_DS
FTDI_JTAG_ON_3: R635.1 S8.3(A3) S9.3(A3) U57.9(~{OE}) ; port FTDI_En_Buff.En_Uart1_2
FTDI_JTAG_ON_4: R721.1 S8.4(A4) S9.4(A4) U79.9(~{OE}) ; port FTDI_En_Buff.En_Uart0
FTDI_LS_UART0_RXD: R1039.2 U79.4(A2)
FTDI_LS_UART0_TXD: R1038.2 U79.3(A1)
FTDI_LS_UART2_CTS_B: R1011.1 U55.41(CDBUS3)
FTDI_LS_UART2_RTS_B: R1010.1 U55.40(CDBUS2)
FTDI_LS_UART2_RXD: R1045.2 U57.6(A4)
FTDI_LS_UART2_TXD: R1044.2 U57.5(A3)
FTDI_LS_UART_RXD: R1047.2 U57.4(A2)
FTDI_LS_UART_TXD: R1046.2 U57.3(A1)
FTDI_PS_POR: R1036.2 U77.1(A1)
FTDI_PS_SRST+B: R1037.2 U77.3(A2)
FTDI_Sock_GND: C558.4(GND) FB32.2
FTDI_TCK: P12.7 R733.1 R1030.2 U53.5(A3) U56.5(A3)
FTDI_TDI: P12.11 R730.1 R1031.2 U53.3(A1) U56.3(A1)
FTDI_TDO: P12.5 R732.1 R1032.2 U53.6(A4) U56.6(A4)
FTDI_TMS: P12.9 R734.1 R1033.2 U53.4(A2) U56.4(A2)
FTDI_VBUS: C558.1(VCC) FB31.2
FTDI_VCC1P8: C665.2 C666.2 C667.2 C673.2 U55.12(VCORE) U55.37(VCORE) U55.49(VREGOUT) U55.64(VCORE)
FTDI_VccIO: C658.2 C668.2 C669.2 C670.2 C671.2 C791.2 FB43.1 FB44.1 R401.2 R402.1 R404.1 R406.1 R408.1 R410.2 R411.1 R413.1 R415.1 R417.1 R418.1 R420.1 R422.2 R424.1 R635.2 R636.1 R638.1 R640.1 R642.1 R721.2 R722.1 R724.1 R726.1 R728.1 R1048.1 R1049.1 R1050.1 R1051.1 U53.16(VCCA) U54.6(VCC) U55.20(VCCIO) U55.31(VCCIO) U55.42(VCCIO) U55.50(VREGIN) U55.56(VCCIO) U56.16(VCCA) U57.16(VCCA) U77.5(VCC) U79.16(VCCA) ; sheet 5V_to_3V3_for_FTDI/Power_Out_3.3V
FTDI_X_IN: C663.2 U55.2(OSCI) X8.1(IN/OUT)
FTDI_X_OUT: C664.2 U55.3(OSCO) X8.3(OUT/IN)
JTAG_CLK: R1042.1 ; port JTAG_DS.JTAG_CLK
JTAG_TDI: R1040.1 ; port JTAG_DS.JTAG_TDI
JTAG_TDO: R1043.1 ; port JTAG_DS.JTAG_TDO
JTAG_TMS: R1041.1 ; port JTAG_DS.JTAG_TMS
PS_POR: U77.6(Y1) ; port PS_POR_B
PS_SRST_B: U77.4(Y2) U78.6(Y1) ; port PS_Reset  [project net PS_Reset]
US2_FTDI_UART1_RXD: U79.13(B2) ; port uart1.TxD
US2_FTDI_UART1_TXD: U79.14(B1) ; port uart1.RxD
US+_MGTVccAux: U79.15(VCCB) ; port VCC_HP_HD_1V8
US_FTDI_UART2_RXD: U57.11(B4) ; harness uart.RxD  [project net uart0_TxD]
US_FTDI_UART2_TXD: U57.12(B3) ; harness uart.TxD  [project net uart0_RxD]
US_FTDI_UART_RXD: U57.13(B2) ; harness uart.RxD  [project net uart1_RxD]
US_FTDI_UART_TXD: U57.14(B1) ; harness uart.TxD  [project net uart1_TxD]
US_PS_JTAG_TCK: R1028.2 ; port JTAG_US.JTAG_CLK
US_PS_JTAG_TDI: R1026.2 ; port JTAG_US.JTAG_TDI
US_PS_JTAG_TDO: R1029.2 ; port JTAG_US.JTAG_TDO
US_PS_JTAG_TMS: R1027.2 ; port JTAG_US.JTAG_TMS
VPHY_FTDI: C661.2 C662.2 FB44.2 U55.4(VPHY)
VPLL_FTDI: C659.2 C660.2 FB43.2 U55.9(VPLL)
NetC558_Z1: C558.Z1(Shield) C558.Z2(Shield) C672.2
NetP12_3: P12.3 R731.1 U78.1(A1)
NetR419_2: R419.2 R422.1 U54.1(DO)
NetR423_1: R423.1 U55.6(REF)
NetR424_2: R424.2 U55.14(RESET#)
NetR1004_1: R1004.1 U55.28(BDBUS2)
NetR1004_2: R1004.2 SP66.1
NetR1005_1: R1005.1 U55.29(BDBUS3)
NetR1005_2: R1005.2 SP67.1
NetR1006_1: R1006.1 U55.30(BDBUS4)
NetR1006_2: R1006.2 SP68.1
NetR1007_1: R1007.1 U55.32(BDBUS5)
NetR1007_2: R1007.2 SP69.1
NetR1008_1: R1008.1 U55.33(BDBUS6)
NetR1008_2: R1008.2 SP70.1
NetR1009_1: R1009.1 U55.34(BDBUS7)
NetR1009_2: R1009.2 SP71.1
NetR1010_2: R1010.2 SP72.1
NetR1011_2: R1011.2 SP73.1
NetR1012_1: R1012.1 U55.43(CDBUS4)
NetR1012_2: R1012.2 SP74.1
NetR1013_1: R1013.1 U55.44(CDBUS5)
NetR1013_2: R1013.2 SP75.1
NetR1014_1: R1014.1 U55.45(CDBUS6)
NetR1014_2: R1014.2 SP76.1
NetR1015_1: R1015.1 U55.46(CDBUS7)
NetR1015_2: R1015.2 SP77.1
NetR1016_1: R1016.1 U55.53(DDBUS2)
NetR1016_2: R1016.2 SP78.1
NetR1017_1: R1017.1 U55.54(DDBUS3)
NetR1017_2: R1017.2 SP79.1
NetR1018_1: R1018.1 U55.55(DDBUS4)
NetR1018_2: R1018.2 SP80.1
NetR1019_1: R1019.1 U55.57(DDBUS5)
NetR1019_2: R1019.2 SP81.1
NetR1020_1: R1020.1 U55.58(DDBUS6)
NetR1020_2: R1020.2 SP82.1
NetR1021_1: R1021.1 U55.59(DDBUS7)
NetR1021_2: R1021.2 SP83.1
NetR1022_1: R1022.1 SP84.1
NetR1022_2: R1022.2 U79.5(A3)
NetR1023_1: R1023.1 U79.12(B3)
NetR1023_2: R1023.2 SP85.1
NetR1024_1: R1024.1 SP86.1
NetR1024_2: R1024.2 U79.6(A4)
NetR1025_1: R1025.1 U79.11(B4)
NetR1025_2: R1025.2 SP87.1
NetR1026_1: R1026.1 U53.14(B1)
NetR1027_1: R1027.1 U53.13(B2)
NetR1028_1: R1028.1 U53.12(B3)
NetR1029_1: R1029.1 U53.11(B4)
NetR1030_1: R1030.1 U55.16(ADBUS0)
NetR1031_1: R1031.1 U55.17(ADBUS1)
NetR1032_1: R1032.1 U55.18(ADBUS2)
NetR1033_1: R1033.1 U55.19(ADBUS3)
NetR1034_1: R1034.1 U55.21(ADBUS4)
NetR1035_1: R1035.1 U55.22(ADBUS5)
NetR1035_2: R1035.2 SP65.1
NetR1036_1: R1036.1 U55.23(ADBUS6)
NetR1037_1: R1037.1 U55.24(ADBUS7)
NetR1038_1: R1038.1 U55.26(BDBUS0)
NetR1039_1: R1039.1 U55.27(BDBUS1)
NetR1040_2: R1040.2 U56.14(B1)
NetR1041_2: R1041.2 U56.13(B2)
NetR1042_2: R1042.2 U56.12(B3)
NetR1043_2: R1043.2 U56.11(B4)
NetR1044_1: R1044.1 U55.38(CDBUS0)
NetR1045_1: R1045.1 U55.39(CDBUS1)
NetR1046_1: R1046.1 U55.48(DDBUS0)
NetR1047_1: R1047.1 U55.52(DDBUS1)
NetR1048_2: R1048.2 S8.8(B1)
NetR1049_2: R1049.2 S8.7(B2)
NetR1050_2: R1050.2 S8.6(B3)
NetR1051_2: R1051.2 S8.5(B4)

Not connected (* = marked no-connect by the designer): P12 13; U55 36(SUSPEND#)* 60(PWREN#)*; U78 3(A2)* 4(Y2)*

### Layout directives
net class Power_Line_2A: FTDI_5V, FTDI_VBUS, FTDI_VccIO
net class USB_FTDI_D: FTDI_D_N, FTDI_D_P
differential pair; differential pair class Diff_90: FTDI_D_N, FTDI_D_P
net class Single_45: FTDI_D_N, FTDI_D_P
net class UART_FTDI_US2: US2_FTDI_UART1_RXD, US2_FTDI_UART1_TXD
net class UART_FTDI_US1_2: US_FTDI_UART2_RXD, US_FTDI_UART2_TXD
net class UART_FTDI_US1_1: US_FTDI_UART_RXD, US_FTDI_UART_TXD
net class UART_FTDI_LS_0: FTDI_LS_UART0_RXD, FTDI_LS_UART0_TXD
net class UART_FTDI_LS_2: FTDI_LS_UART2_RXD, FTDI_LS_UART2_TXD
net class UART_FTDI_LS_1: FTDI_LS_UART_RXD, FTDI_LS_UART_TXD
net class JTAG_FTDI: FTDI_TCK, FTDI_TDI, FTDI_TDO, FTDI_TMS

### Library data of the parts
C558 = WE-Communication Connectors 61400413321: WR-COM USB Vertical Type B; Manufacturer: Würth Elektronik eiSos GmbH; ComponentLink1 Description: Manufacturer; ComponentLink2 Description: Datasheet; NoPins: 4
C559 = Capacitor: as C485 on sheet RJ45
C560 C659 C661 = Capacitor: Manufacturer: Samsung; Manufacturer Part Number: CL10A475KP8NNNC; Tolerance: 10%; Voltage Rating: 10V
C658 C660 C662 C665-C671 C673 C791 C792 = Capacitor: as C471-C474 on sheet RJ45
C663 C664 = Capacitor: as C480 on sheet RJ45
C672 = Capacitor_1210: as C475 on sheet RJ45
D15 = TPD2EUSB30DRTR: TVS DIODE 5.5V 8V SOT3; Manufacturer: Texas Instruments; Direction: Unidirectional,Bidirectional; Capacitance: 0.8pF; Number of Bidirectional Channels: 2; Min Breakdown Voltage: 9V; Peak Pulse Power: 45W; Power Line Protection: Yes; Test Current: 1mA; Element Configuration: Dual; Peak Pulse Current: 1A; Interface: USB
FB31 FB32 FB43 FB44 = Ferrite: as FB29 on sheet uSD
P12 = Header 7X2: SAMTEC         HTSW-107-08-T-D-RA             Board-To-Board Connector, Right Angle, HTSW Series, 14 Contacts, Header, 2.54 mm, Through Hole; Max Current Rating: 7.6A; Number of Contacts: 14; Max Voltage Rating (AC): 450V; Gender: Male; Pitch: 2.54mm
R401 R410 R417 R420 R422 R635 R721 = Resistor: SMT Resistor
R402-R409 R411-R416 R418 R421 R636-R643 R722-R729 R1001 R1004-R1047 = Resistor: as R711-R713 on sheet RJ45
R419 = Resistor: RES SMD 2K OHM 1% 1/16W 0402; Manufacturer: Yageo; Manufacturer Part Number: RC0402FR-072KL; Power Rating: 63mW; Voltage Rating: 50V; Temperature Coefficient: 100ppm/°C
R423 = Resistor: CRGCQ 0402 12K 1%; Manufacturer: TE Connectivity; Manufacturer Part Number: CRGCQ0402F12K
R424 R1048-R1051 = Resistor: Manufacturer: Panasonic; Manufacturer Part Number: ERJ-2RKF1001X; Tolerance: 1%; Power Rating: 100mW; Temperature Coefficient: 100ppm/°C; Voltage Rating: 50V
R730-R734 = Resistor: as R381 on sheet uSD
S8 S9 = SW DIP-4: Manufacturer: CTS; Manufacturer Part Number: 218-4LPSTR; Mechanical Life: 1000Cycles; Actuator Type: Slide (Standard); Number of Positions: 4; Pitch: 0.05inch; Washable: Yes
U53 U56 U57 U79 = SN74AXC4T774PWR: Manufacturer 1: Texas Instruments
U54 = 93LC56BT-I/OT: MICROCHIP - 93LC56BT-I/OT. - 2K, 128 X 16, SERIAL EE, IND ROHS COMPLIANT: YES; Density: 2Kb; Max Supply Voltage: 5.5V; Min Supply Voltage: 2.5V; Access Time: 250ns; Frequency: 2MHz; Nominal Supply Current: 2mA; Memory Type: EEPROM
U55 = FT4232HL-REEL: IC USB HS QUAD UART/SYNC 64-LQFP; Manufacturer 1: FTDI; Number of Channels: 1; Max Supply Voltage: 3.63V; Min Supply Voltage: 1.62V; Data Rate: 480Mbps; Operating Supply Voltage: 3.3V; Interface: UART; Operating Supply Current: 70mA; Number of Transceivers: 4; ESD Protection: Yes
U77 U78 = NC7WZ07FHX: Buffer/Driver 2-CH Non-Inverting Open Drain CMOS 6-Pin MicroPak T/R; Manufacturer: ON Semiconductor / Fairchild; Number of Channels: 2; Max Supply Voltage: 5.5V; Min Supply Voltage: 1.65V; Propagation Delay: 12.6ns; Logic Function: Buffer,Inverting; Low Level Output Current: 32mA; Number of Bits per Element: 1; Quiescent Current: 1uA; Schmitt Trigger Input: No
X8 = ECS-120-8-33-RWY-TR: Manufacturer 1: ECS International

## Sheet USB3.SchDoc
size A3; Organization: Altium Limited; Address1: L3, 12a Rodborough Rd; Address2: Frenchs Forest; Address3: NSW; Address4: Australia 2086
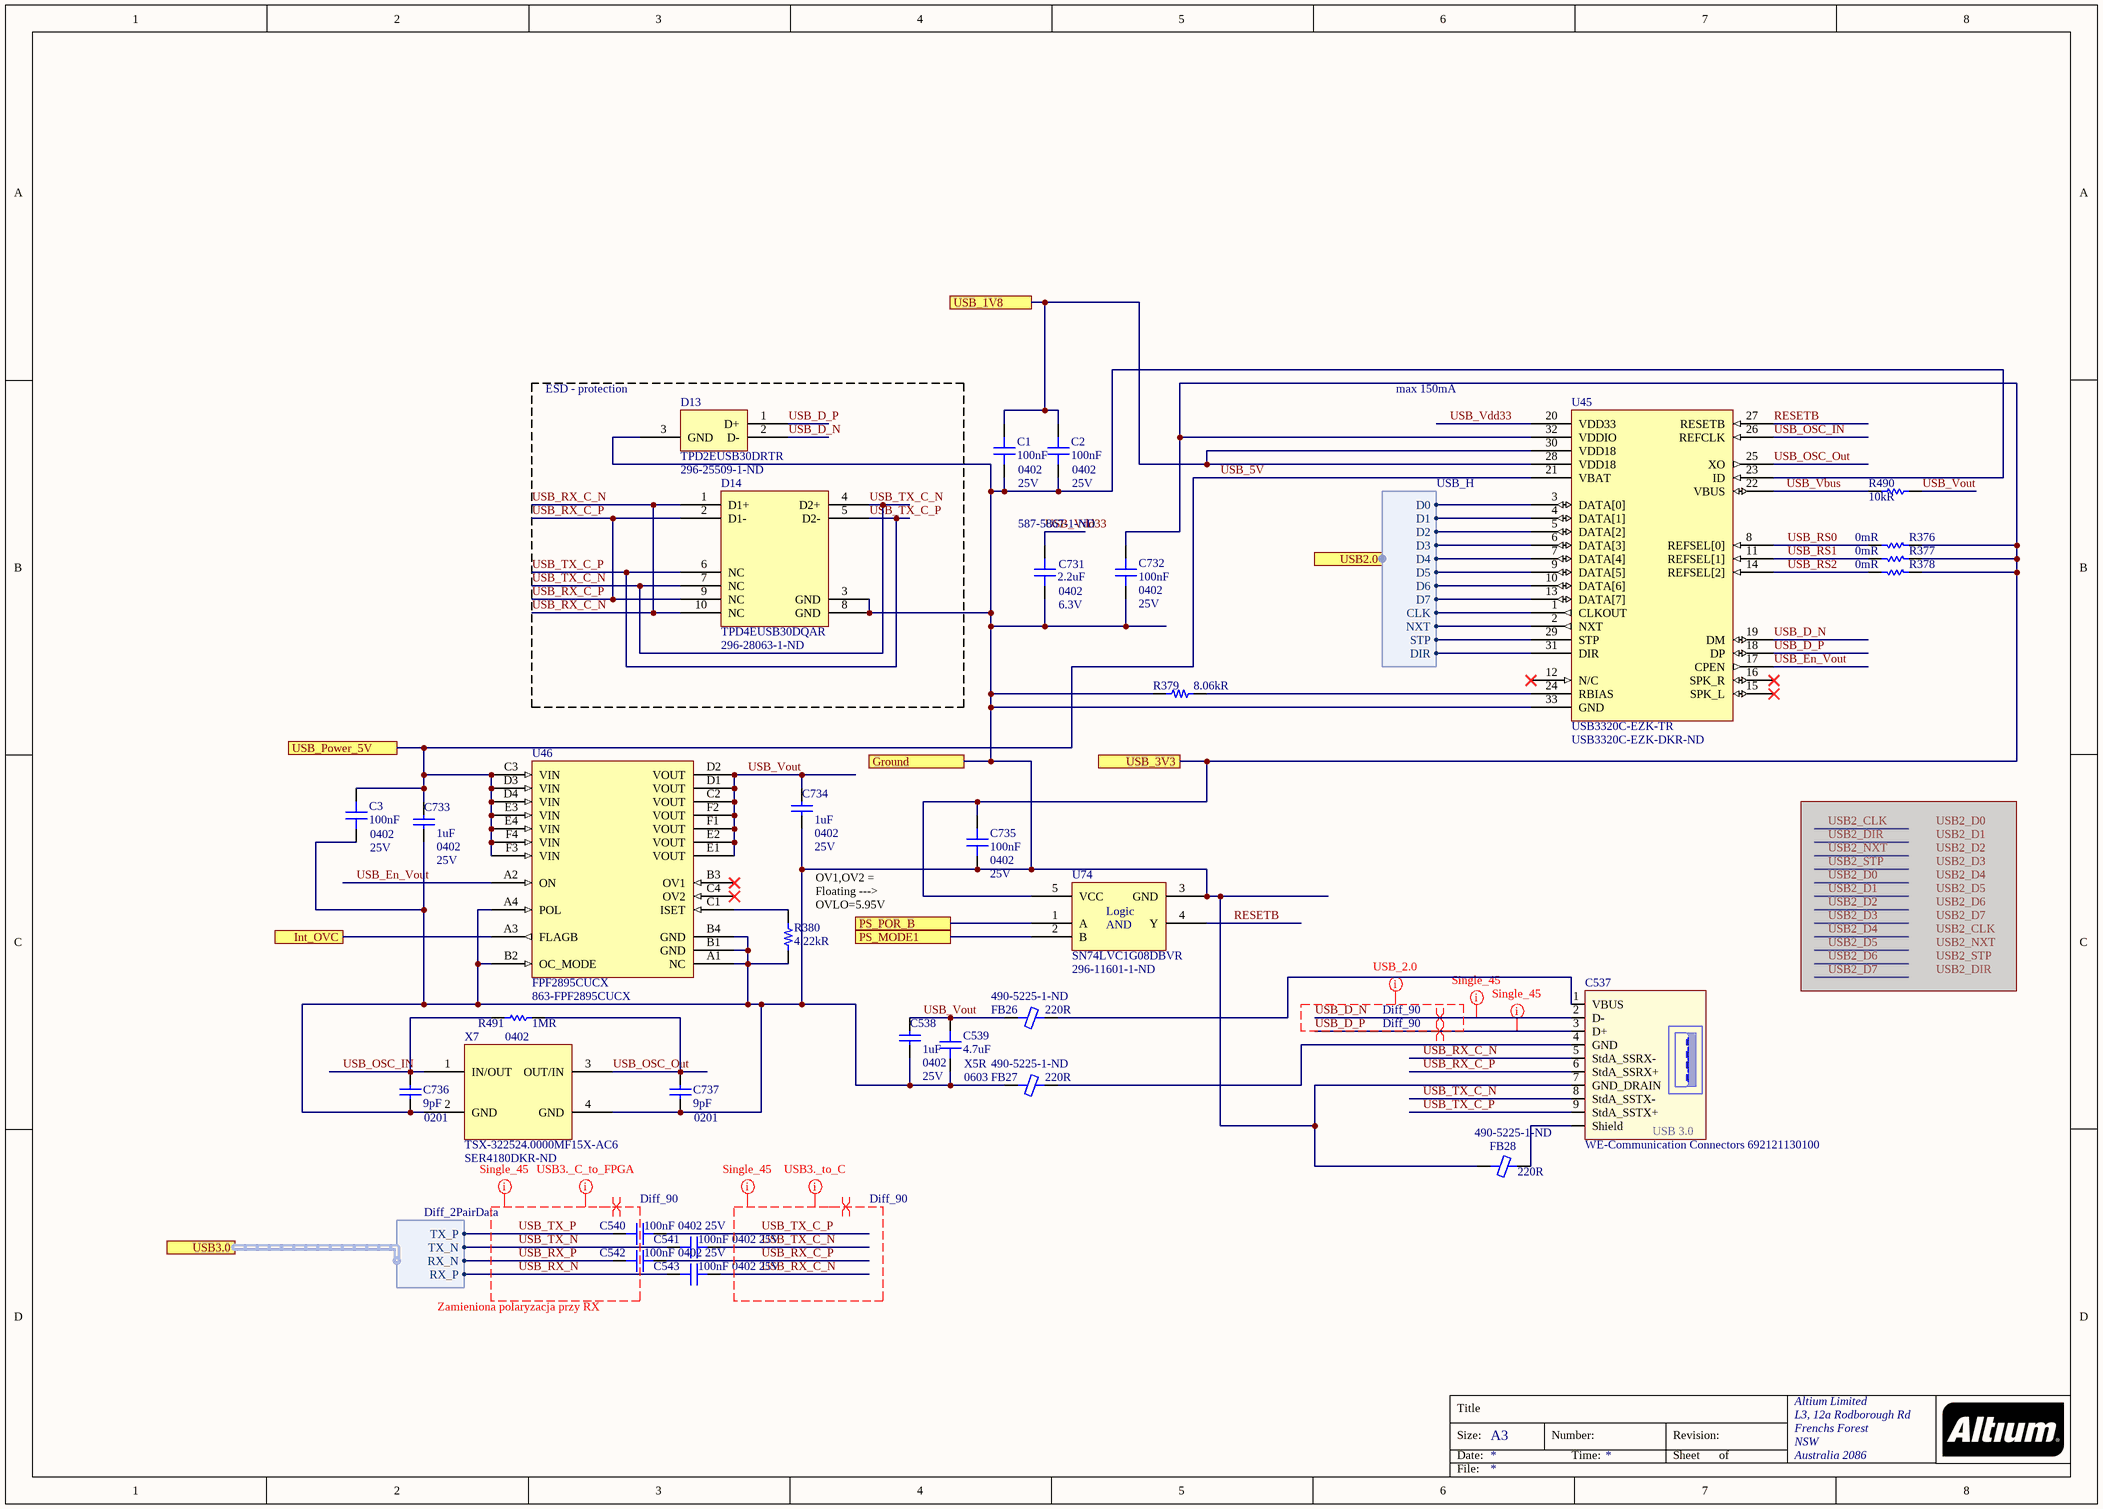
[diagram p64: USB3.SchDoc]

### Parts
C1  100nF  Case/Package: 0402  Voltage Rating: 25V  [CAP 0402/1005 KK]
C2  100nF  Case/Package: 0402  Voltage Rating: 25V  [CAP 0402/1005 KK]
C3  100nF  Case/Package: 0402  Voltage Rating: 25V  [CAP 0402/1005 KK]
C537  WE-Communication Connectors 692121130100  [692121130100]
C538  1uF  Case/Package: 0402  Voltage Rating: 25V  [CAP 0402/1005 KK]
C539  4.7uF  Case/Package: 0603  Dielectric: X5R  [CAP 0603/1608 RF]
C540  100nF  Case/Package: 0402  Voltage Rating: 25V  [CAP 0402/1005 KK]
C541  100nF  Case/Package: 0402  Voltage Rating: 25V  [CAP 0402/1005 KK]
C542  100nF  Case/Package: 0402  Voltage Rating: 25V  [CAP 0402/1005 KK]
C543  100nF  Case/Package: 0402  Voltage Rating: 25V  [CAP 0402/1005 KK]
C731  2.2uF  Supplier Part Number 1: 587-5867-1-ND  Case Code (Imperial): 0402  Voltage Rating: 6.3V  [CAP 0402/1005 KK]
C732  100nF  Case/Package: 0402  Voltage Rating: 25V  [CAP 0402/1005 KK]
C733  1uF  Case/Package: 0402  Voltage Rating: 25V  [CAP 0402/1005 KK]
C734  1uF  Case/Package: 0402  Voltage Rating: 25V  [CAP 0402/1005 KK]
C735  100nF  Case/Package: 0402  Voltage Rating: 25V  [CAP 0402/1005 KK]
C736  9pF  Case/Package: 0201  [CAP 0201/0603 KK]
C737  9pF  Case/Package: 0201  [CAP 0201/0603 KK]
D13  TPD2EUSB30DRTR  Supplier Part Number 1: 296-25509-1-ND  [TPD2EUSB30]
D14  TPD4EUSB30DQAR  Supplier Part Number 1: 296-28063-1-ND  [TPD4EUSB30]
FB26  220R  Supplier Part Number 1: 490-5225-1-ND  [FER 0603/1608]
FB27  220R  Supplier Part Number 1: 490-5225-1-ND  [FER 0603/1608]
FB28  220R  Supplier Part Number 1: 490-5225-1-ND  [FER 0603/1608]
R376  0mR  [RES 0402/1005 RF KK]
R377  0mR  [RES 0402/1005 RF KK]
R378  0mR  [RES 0402/1005 RF KK]
R379  8.06kR  [RES 0402/1005 RF KK]
R380  4.22kR  [RES 0402/1005 RF KK]
R490  10kR  [RES 0402/1005 RF KK]
R491  1MR  Case/Package: 0402  [RES 0402/1005 RF KK]
U45  USB3320C-EZK-TR  Supplier Part Number 1: USB3320C-EZK-DKR-ND  [USB3320]
U46  FPF2895CUCX  Supplier Part Number 1: 863-FPF2895CUCX  [FPF2895C-D]
U74  SN74LVC1G08DBVR  Supplier Part Number 1: 296-11601-1-ND  [SN74LVC1G08DBVR]
X7  TSX-322524.0000MF15X-AC6  Supplier Part Number 1: SER4180DKR-ND  [TSX-3225 24.0000MF15X-AC6]

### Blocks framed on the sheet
ESD - protection: D13 D14

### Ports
Ground, Int_OVC, PS_MODE1, PS_POR_B, USB2.0 (harness USB_H), USB3.0 (harness Diff_2PairData), USB_1V8, USB_3V3, USB_Power_5V

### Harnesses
Diff_2PairData: RX_P, RX_N, TX_P, TX_N
USB_H: CLK, DIR, NXT, STP, D0, D1, D2, D3, D4, D5, D6, D7

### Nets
B503_Ground: C1.1 C2.1 C3.1 C537.7(GND_DRAIN) C538.2 C539.1 C731.1 C732.2 C733.2 C734.2 C735.2 C736.1 C737.1 D13.3(GND) D14.3(GND) D14.8(GND) FB27.1 FB28.1 R379.1 R380.1 U45.23(ID) U45.33(GND) U46.A1(NC) U46.A4(POL) U46.B1(GND) U46.B2(OC_MODE) U46.B4(GND) U74.3(GND) X7.2(GND) X7.4(GND) ; port Ground
1V8@1.5A: C1.2 C2.2 U45.28(VDD18) U45.30(VDD18) ; port USB_1V8
3V3_RAIL: C732.1 C735.1 R376.2 R377.2 R378.2 U45.32(VDDIO) U74.5(VCC) ; port USB_3V3
GPIOa_01.GPIO5: U46.A3(FLAGB) ; port Int_OVC
PS_MODE1: U74.2(B) ; port PS_MODE1
PS_POR: U74.1(A) ; port PS_POR_B
RESETB: U45.27(RESETB) U74.4(Y)
USB2_CLK: U45.1(CLKOUT) ; port USB2.0.CLK
USB2_D0: U45.3(DATA[0]) ; port USB2.0.D0
USB2_D1: U45.4(DATA[1]) ; port USB2.0.D1
USB2_D2: U45.5(DATA[2]) ; port USB2.0.D2
USB2_D3: U45.6(DATA[3]) ; port USB2.0.D3
USB2_D4: U45.7(DATA[4]) ; port USB2.0.D4
USB2_D5: U45.9(DATA[5]) ; port USB2.0.D5
USB2_D6: U45.10(DATA[6]) ; port USB2.0.D6
USB2_D7: U45.13(DATA[7]) ; port USB2.0.D7
USB2_DIR: U45.31(DIR) ; port USB2.0.DIR
USB2_NXT: U45.2(NXT) ; port USB2.0.NXT
USB2_STP: U45.29(STP) ; port USB2.0.STP
USB_5V: C3.2 C733.1 U45.21(VBAT) U46.C3(VIN) U46.D3(VIN) U46.D4(VIN) U46.E3(VIN) U46.E4(VIN) U46.F3(VIN) U46.F4(VIN) ; port USB_Power_5V  [project net 5V_RAIL]
USB_D_N: C537.2(D-) D13.2(D-) U45.19(DM)
USB_D_P: C537.3(D+) D13.1(D+) U45.18(DP)
USB_En_Vout: U45.17(CPEN) U46.A2(ON)
USB_OSC_IN: C736.2 R491.2 U45.26(REFCLK) X7.1(IN/OUT)
USB_OSC_Out: C737.2 R491.1 U45.25(XO) X7.3(OUT/IN)
USB_RS0: R376.1 U45.8(REFSEL[0])
USB_RS1: R377.1 U45.11(REFSEL[1])
USB_RS2: R378.1 U45.14(REFSEL[2])
USB_RX_C_N: C537.5(StdA_SSRX-) C543.1 D14.1(D1+) D14.10(NC)
USB_RX_C_P: C537.6(StdA_SSRX+) C542.1 D14.2(D1-) D14.9(NC)
USB_RX_N: C543.2 ; port USB3.0.RX_P
USB_RX_P: C542.2 ; port USB3.0.RX_N
USB_TX_C_N: C537.8(StdA_SSTX-) C541.1 D14.4(D2+) D14.7(NC)
USB_TX_C_P: C537.9(StdA_SSTX+) C540.1 D14.5(D2-) D14.6(NC)
USB_TX_N: C541.2 ; port USB3.0.TX_N
USB_TX_P: C540.2 ; port USB3.0.TX_P
USB_Vbus: R490.1 U45.22(VBUS)
USB_Vdd33: C731.2 U45.20(VDD33)
USB_Vout: C538.1 C539.2 C734.1 FB26.1 R490.2 U46.C2(VOUT) U46.D1(VOUT) U46.D2(VOUT) U46.E1(VOUT) U46.E2(VOUT) U46.F1(VOUT) U46.F2(VOUT)
NetC537_1: C537.1(VBUS) FB26.2
NetC537_4: C537.4(GND) FB27.2
NetC537_Z1: C537.Z1(Shield) FB28.2
NetR379_2: R379.2 U45.24(RBIAS)
NetR380_2: R380.2 U46.C1(ISET)

Not connected (* = marked no-connect by the designer): U45 12(N/C)* 15(SPK_L)* 16(SPK_R)*; U46 B3(OV1)* C4(OV2)*

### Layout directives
differential pair; differential pair class Diff_90: USB_D_N, USB_D_P, USB_RX_C_N, USB_RX_C_P, USB_RX_N, USB_RX_P, USB_TX_C_N, USB_TX_C_P, USB_TX_N, USB_TX_P
net class Single_45: USB_D_N, USB_D_P, USB_RX_C_N, USB_RX_C_P, USB_RX_N, USB_RX_P, USB_TX_C_N, USB_TX_C_P, USB_TX_N, USB_TX_P
net class USB_2.0: USB_D_N, USB_D_P
net class USB3._to_C: USB_RX_C_N, USB_RX_C_P, USB_TX_C_N, USB_TX_C_P
net class USB3._C_to_FPGA: USB_RX_N, USB_RX_P, USB_TX_N, USB_TX_P

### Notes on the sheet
- max 150mA
- (near R380) OV1,OV2 = Floating ---> OVLO=5.95V
- (near C542) Zamieniona polaryzacja przy RX

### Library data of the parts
C1-C3 C540-C543 C732 C735 = Capacitor: as C479 on sheet RJ45
C537 = WE-Communication Connectors 692121130100: WR-COM USB 3.0 Horizontal Type A; Manufacturer: Würth Elektronik eiSos GmbH; ComponentLink1 Description: Manufacturer; ComponentLink2 Description: Datasheet; NoPins: 9
C538 C733 C734 = Capacitor: as C485 on sheet RJ45
C539 = Capacitor: as C560 on sheet FTDI
C731 = Capacitor: CAP CER 2.2UF 6.3V X5R 0402; Manufacturer: Taiyo Yuden; Manufacturer Part Number: JMK105BJ225KV-F; Tolerance: 10%
C736 C737 = Capacitor: Manufacturer: Murata; Manufacturer Part Number: GRM0335C1E9R0CA01D; Voltage Rating: 25V
D13 = TPD2EUSB30DRTR: as D15 on sheet FTDI
D14 = TPD4EUSB30DQAR: TVS DIODE 5.5V 8V 10SON; Manufacturer: Texas Instruments; Direction: Unidirectional; Capacitance: 0.8pF; Current Rating: 5A; Number of Bidirectional Channels: 4; Peak Pulse Power: 45W; Power Line Protection: Yes; Breakdown Voltage: 7V; Data Rate: 6Gbps; Peak Pulse Current: 1A; Interface: USB
FB26-FB28 = Ferrite: as FB29 on sheet uSD
R376-R378 = Resistor: as R711-R713 on sheet RJ45
R379 = Resistor: RES 8.06K OHM 1% 1/16W 0402; Manufacturer: Stackpole Electronics; Manufacturer Part Number: RMCF0402FT8K06; Max Power Dissipation: 63mW; Temperature Coefficient: 100ppm/°C
R380 = Resistor: Thick Film Resistors 4.22K OHM 1%; Manufacturer: Yageo; Manufacturer Part Number: RC0402FR-074K22L; Temperature Coefficient: 100ppm/°C; Power Rating: 62.5mW; Voltage Rating: 50V; Max Power Dissipation: 63mW
R490 = Resistor: as R319 on sheet RJ45
R491 = Resistor: as R335 on sheet RJ45
U45 = USB3320C-EZK-TR: IC TXRX USB 2.0 FLEXPWR 32QFN; Manufacturer 1: Microchip; Data Rate: 12Mbps; Interface: UART; Operating Supply Current: 18uA; ESD Protection: Yes; Number of Transceivers: 1; Operating Supply Voltage: 5.5V; Frequency: 60MHz; Simplex/Duplex: Half Duplex; Receiver Hysteresis: 50mV
U46 = FPF2895CUCX: Current Limit Load Switch with OVP and TRCB, 28 V, 5 A; Manufacturer 1: ON Semiconductor
U74 = SN74LVC1G08DBVR: as U76 on sheet RJ45
X7 = TSX-322524.0000MF15X-AC6: CRYSTAL 24.00 MHZ 9.0PF SMD; Manufacturer 1: Epson; Frequency: 24MHz; Load Capacitance: 9pF; ESR (Equivalent Series Resistance): 40R; Frequency Stability: 15ppm; Frequency Tolerance: 10ppm

## Sheet CAN.SchDoc
size A4
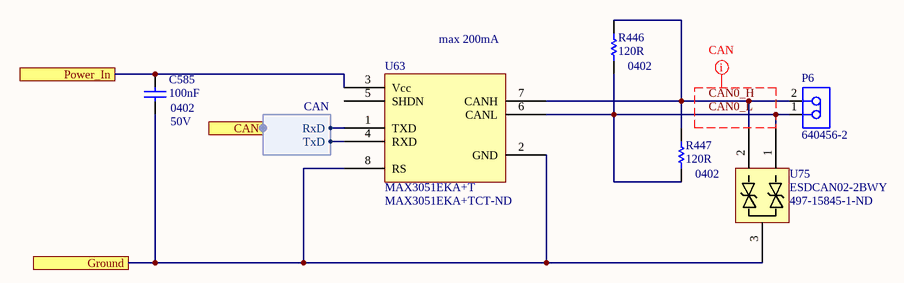
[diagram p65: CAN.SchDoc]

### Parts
C585  100nF  Case Code (Imperial): 0402  Voltage: 50V  [CAP 0402/1005 KK]
P6  640456-2  [TECO-640456-2_V]
R446  120R  Case/Package: 0402  [RES 0402/1005 RF KK]
R447  120R  Case/Package: 0402  [RES 0402/1005 RF KK]
U63  MAX3051EKA+T  Supplier Part Number 1: MAX3051EKA+TCT-ND  [MAX3051EKA+T SOT23]
U75  ESDCAN02-2BWY  Supplier Part Number 1: 497-15845-1-ND  [ESDCAN02-2BWY]

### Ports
CAN (harness CAN), Ground, Power_In

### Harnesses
CAN: RxD, TxD

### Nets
B503_Ground: C585.1 U63.2(GND) U63.8(RS) U75.3 ; port Ground
3V3_RAIL: C585.2 U63.3(Vcc) ; port Power_In
CAN0_H: P6.2 R446.2 R447.2 U63.7(CANH) U75.2
CAN0_L: P6.1 R446.1 R447.1 U63.6(CANL) U75.1
CAN1_RxD: U63.1(TXD) ; port CAN.RxD
CAN1_TxD: U63.4(RXD) ; port CAN.TxD

Not connected (* = marked no-connect by the designer): U63 5(SHDN)

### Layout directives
net class CAN: CAN0_H, CAN0_L

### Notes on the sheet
- (near U63) max 200mA

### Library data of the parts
C585 = Capacitor: as C471-C474 on sheet RJ45
P6 = 640456-2: Male Header, Pitch 2.54 mm, 1 x 2 Position, Height 10.49 mm, Tail Length 3.556 mm, -55 to 105 degC, RoHS, Bulk; Mounting Hole Size: 0.04 / "; Number of Contacts: 2; Primary Type: Interconnect System; Temperature, Operating: -55 to +105 / °C; Pin Spacing: 0.1 / "; Color, Housing: White; Connector Type: MTA-100; Mount Angle: Vertical; Voltage, Rating: 250 / V; Material, Housing: Polyester; Material, Contact: Copper Alloy; Special Features: Pinstrip; Brand/Series: MTA-100 Series; Contact Centerline Spacing: 0.100 / in.; Contact Termination Area Plating: Tin; Agency Approvals: CSA, UL; Angle: Straight; Standards: RoHS Compliant, ELV Compliant, UL 94V-0; Current, Rating: 5 / A
R446 R447 = Resistor: RES SMD 120 OHM 1% 1/16W 0402; Manufacturer: Vishay; Manufacturer Part Number: CRCW0402120RFKED; Temperature Coefficient: 100ppm/°C; Power Rating: 63mW; Voltage Rating: 50V
U63 = MAX3051EKA+T: IC TXRX CAN 1MBPS SOT23-8; Manufacturer: Maxim; Max Supply Voltage: 3.465V; Min Supply Voltage: 3.135V; Operating Supply Current: 35mA; Number of Transceivers: 1; Max Supply Current: 70mA; Operating Supply Voltage: 3.3V
U75 = ESDCAN02-2BWY: TVS DIODE 26.5VWM 44VC SOT323; Manufacturer: STMicroelectronics; Peak Pulse Current: 3A; Number of Bidirectional Channels: 2; Reverse Standoff Voltage: 26.5V; Min Breakdown Voltage: 28.5V; Clamping Voltage: 44V; Peak Pulse Power: 250W; Power Line Protection: No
